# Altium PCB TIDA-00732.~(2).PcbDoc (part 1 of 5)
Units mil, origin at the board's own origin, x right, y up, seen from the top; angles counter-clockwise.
Board outline 8994.78 x 4186 mil, 6 copper layers (Top Layer, GND1, PWR1, PWR2, GND2, Bottom Layer), stack 97.668 mil thick; 693 components, 463 nets, 2087 pads, 616 vias.
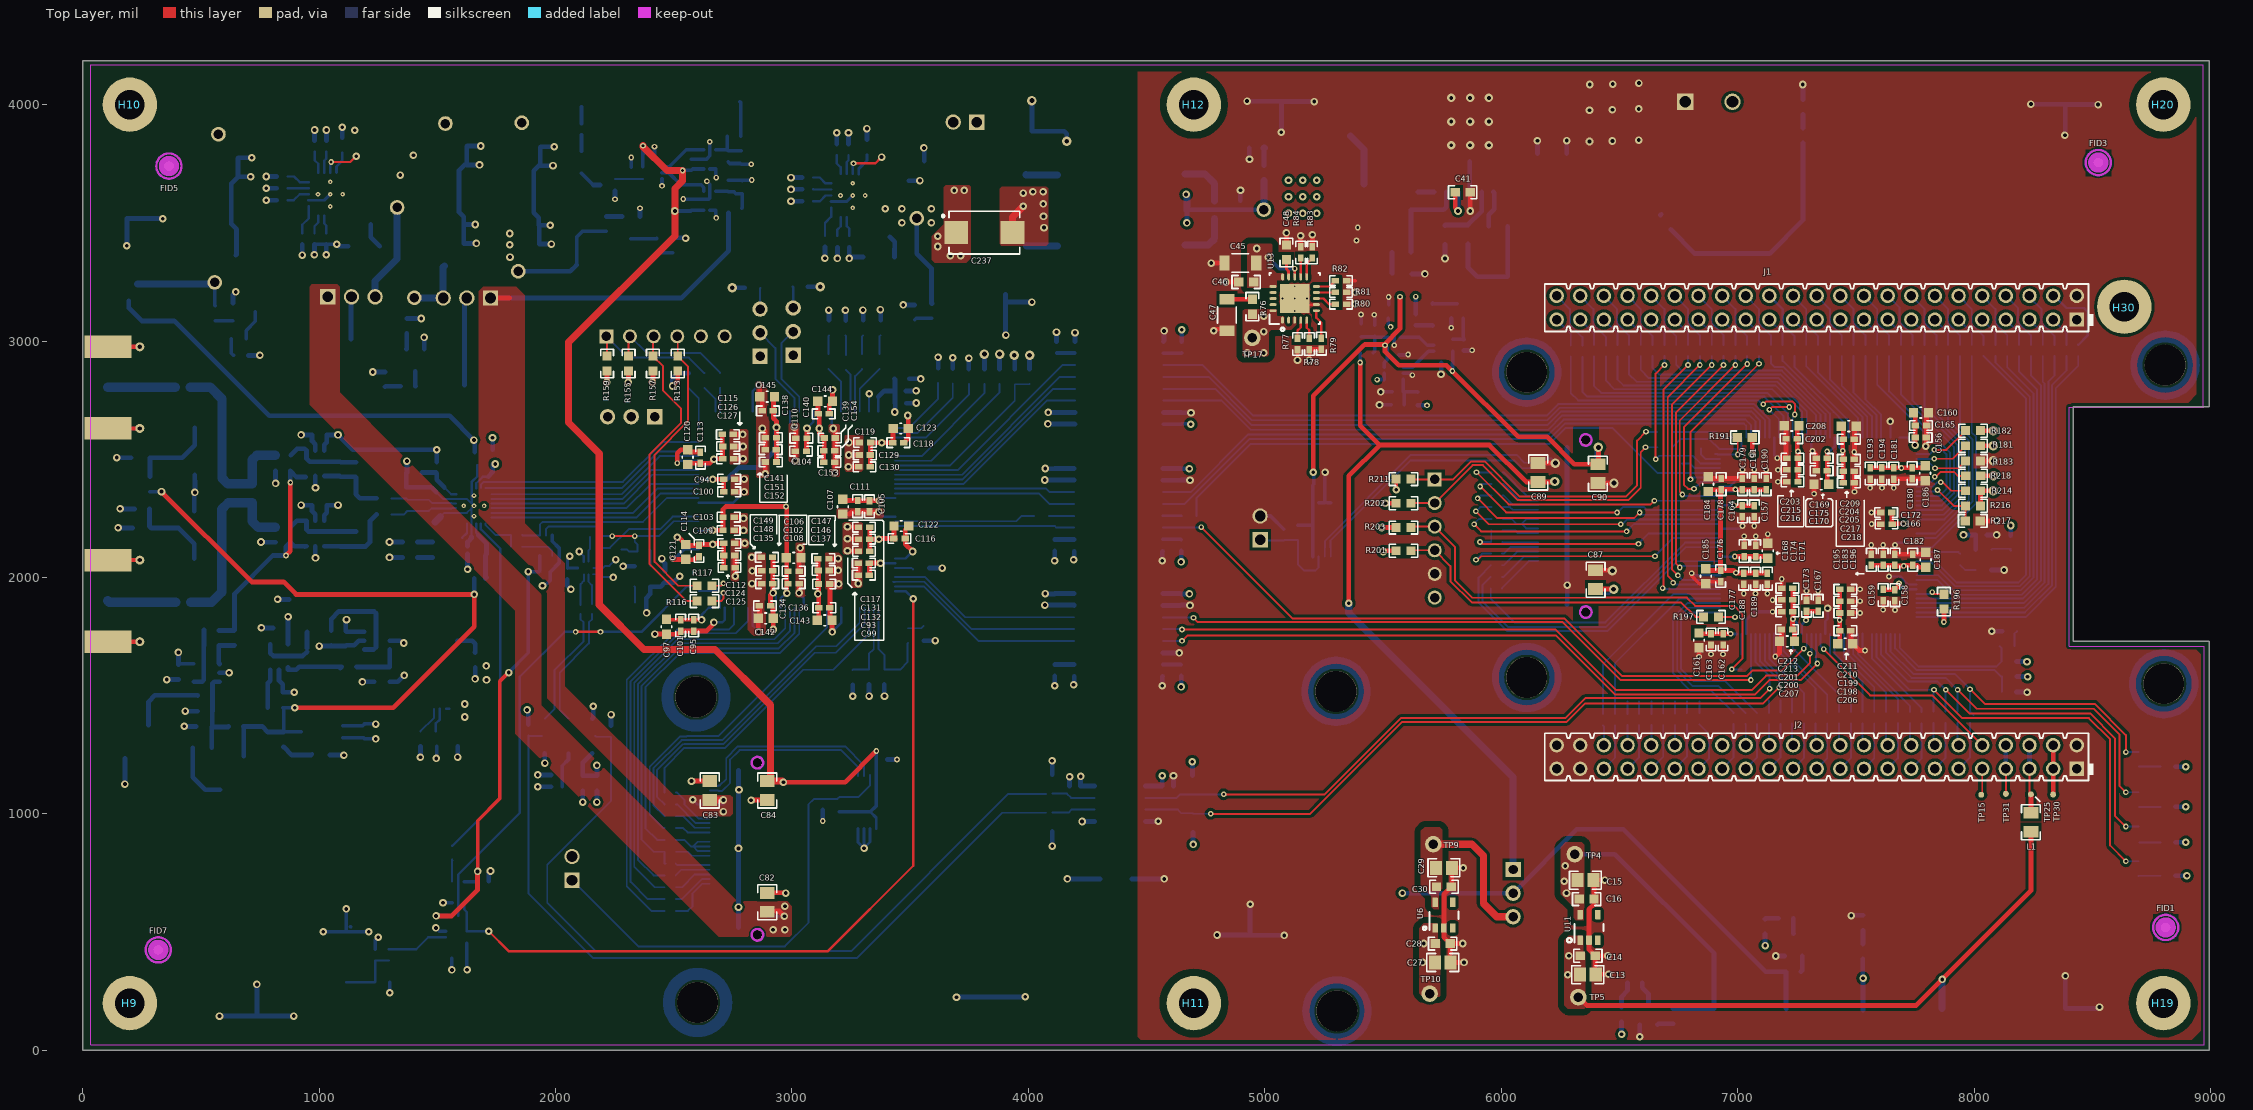
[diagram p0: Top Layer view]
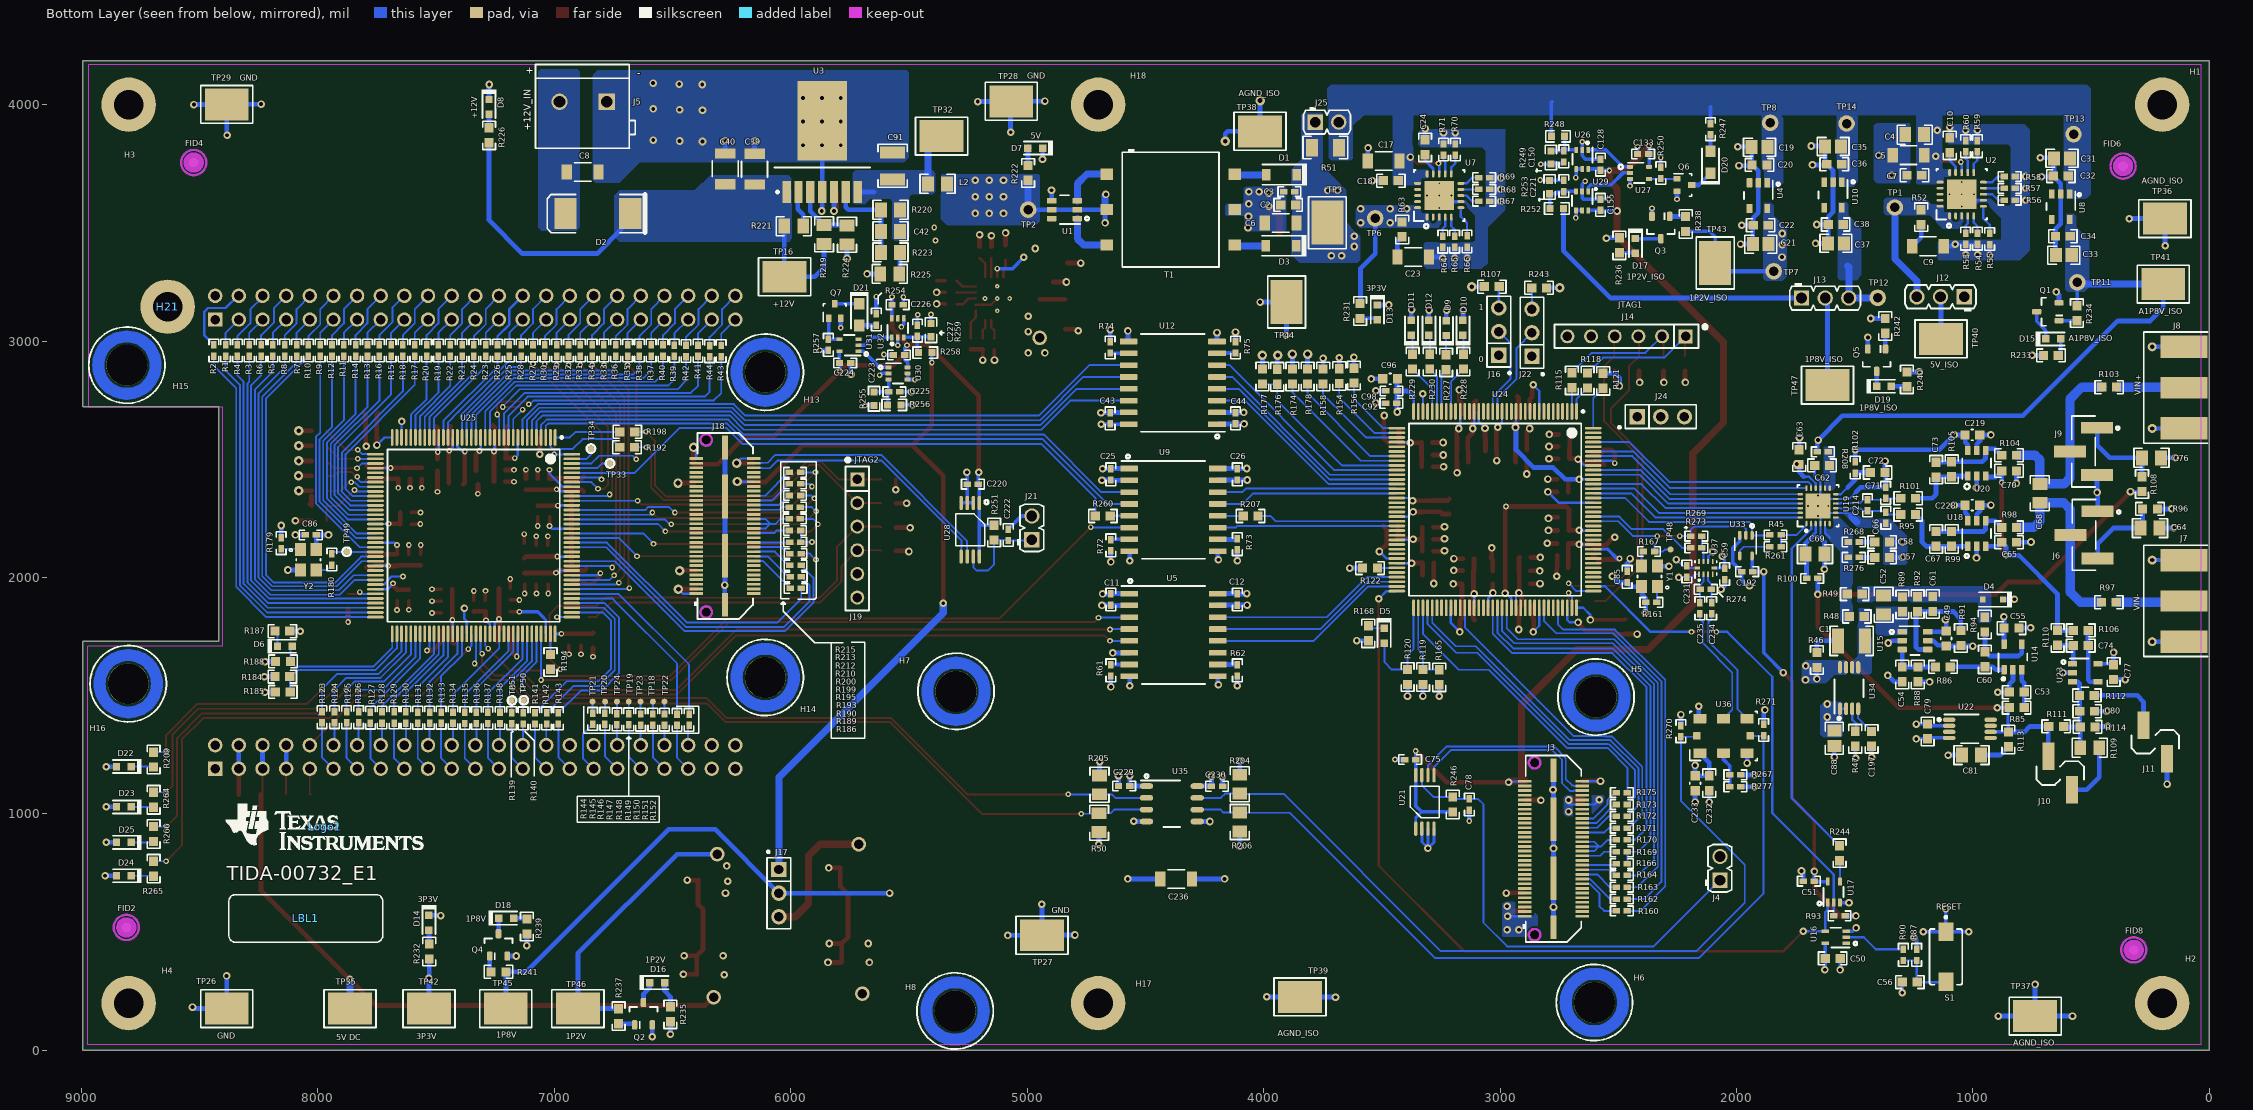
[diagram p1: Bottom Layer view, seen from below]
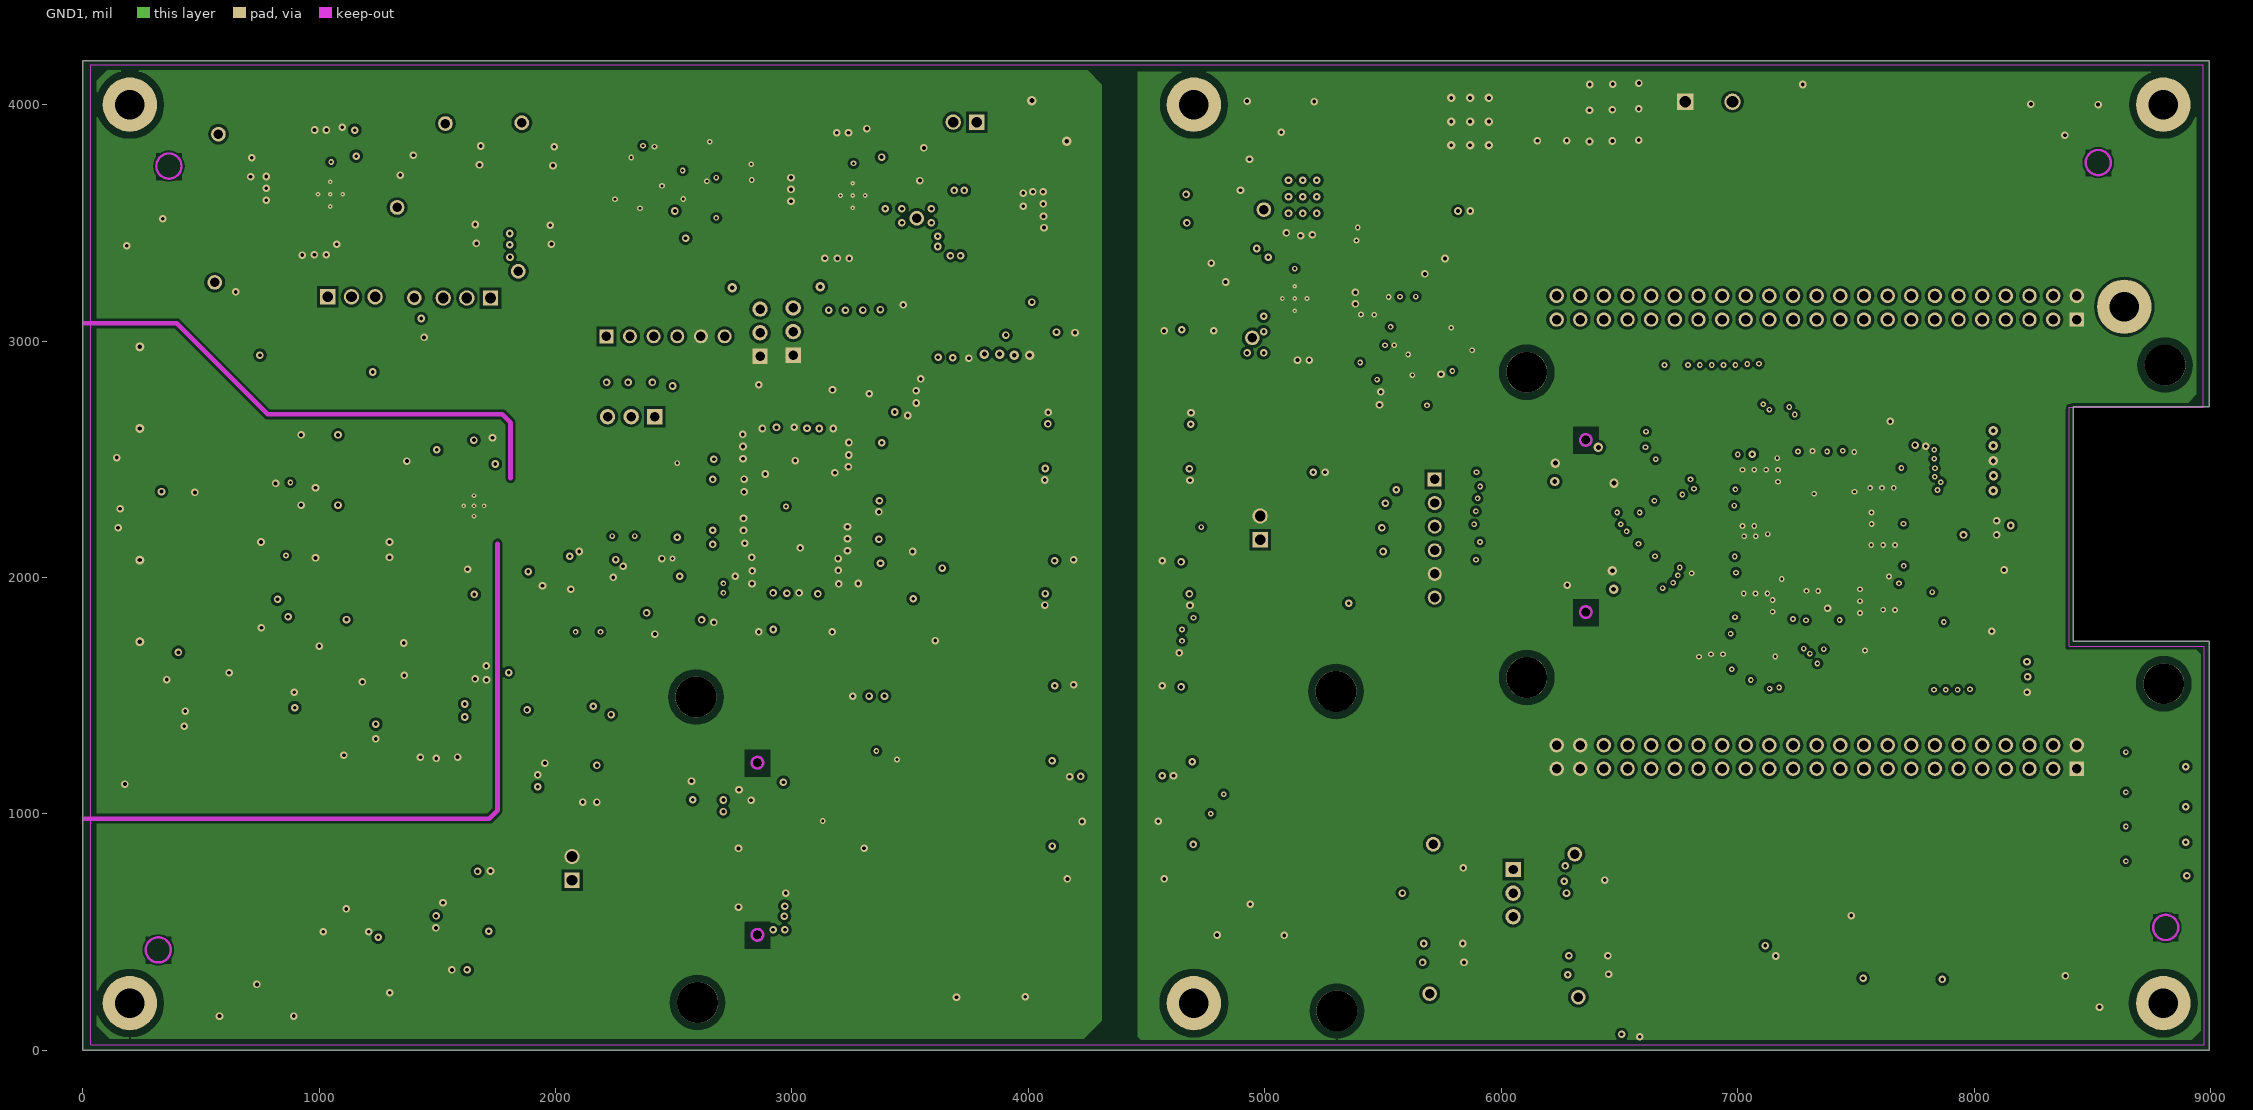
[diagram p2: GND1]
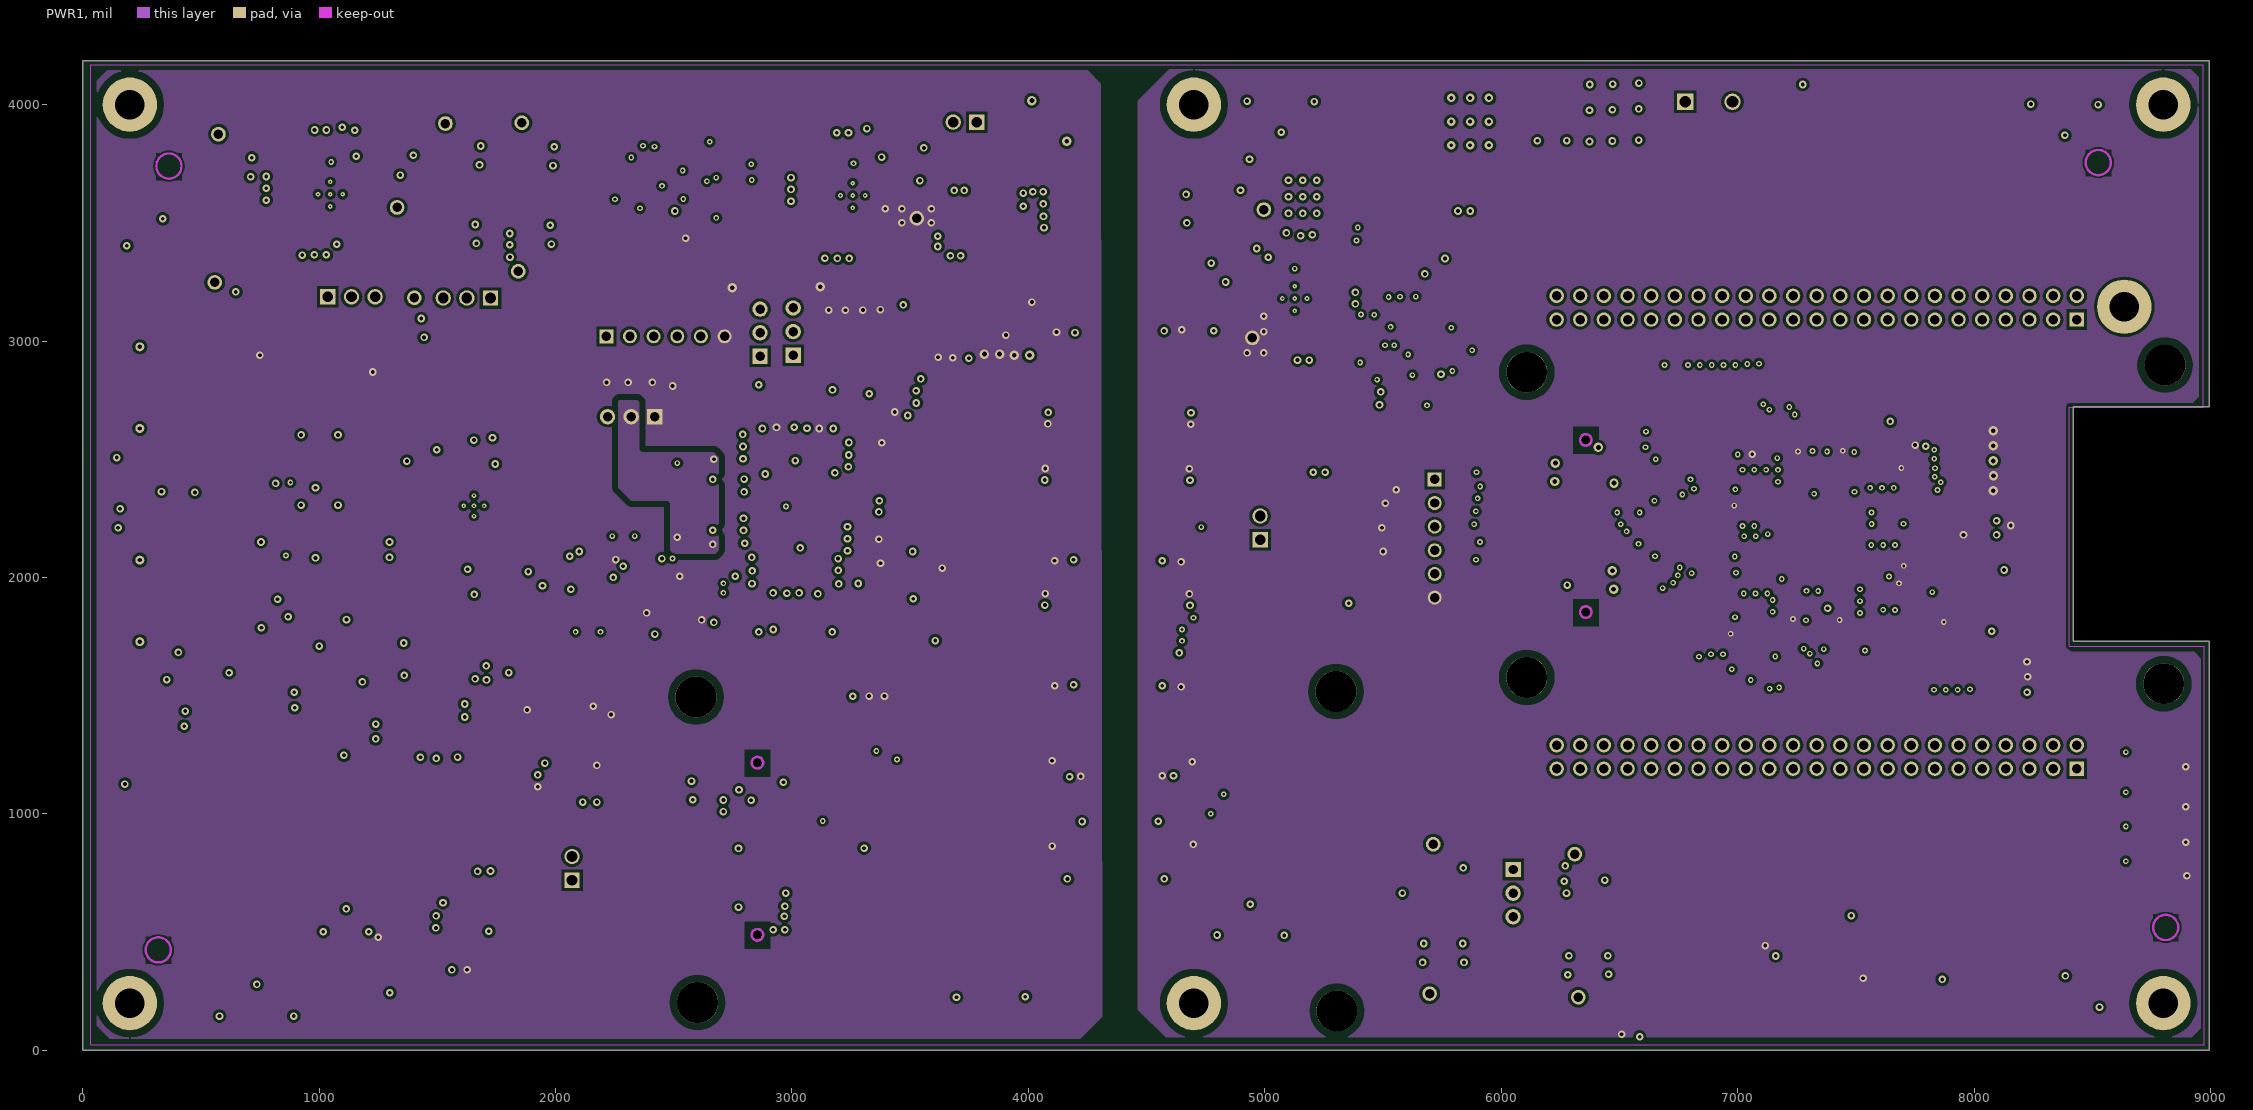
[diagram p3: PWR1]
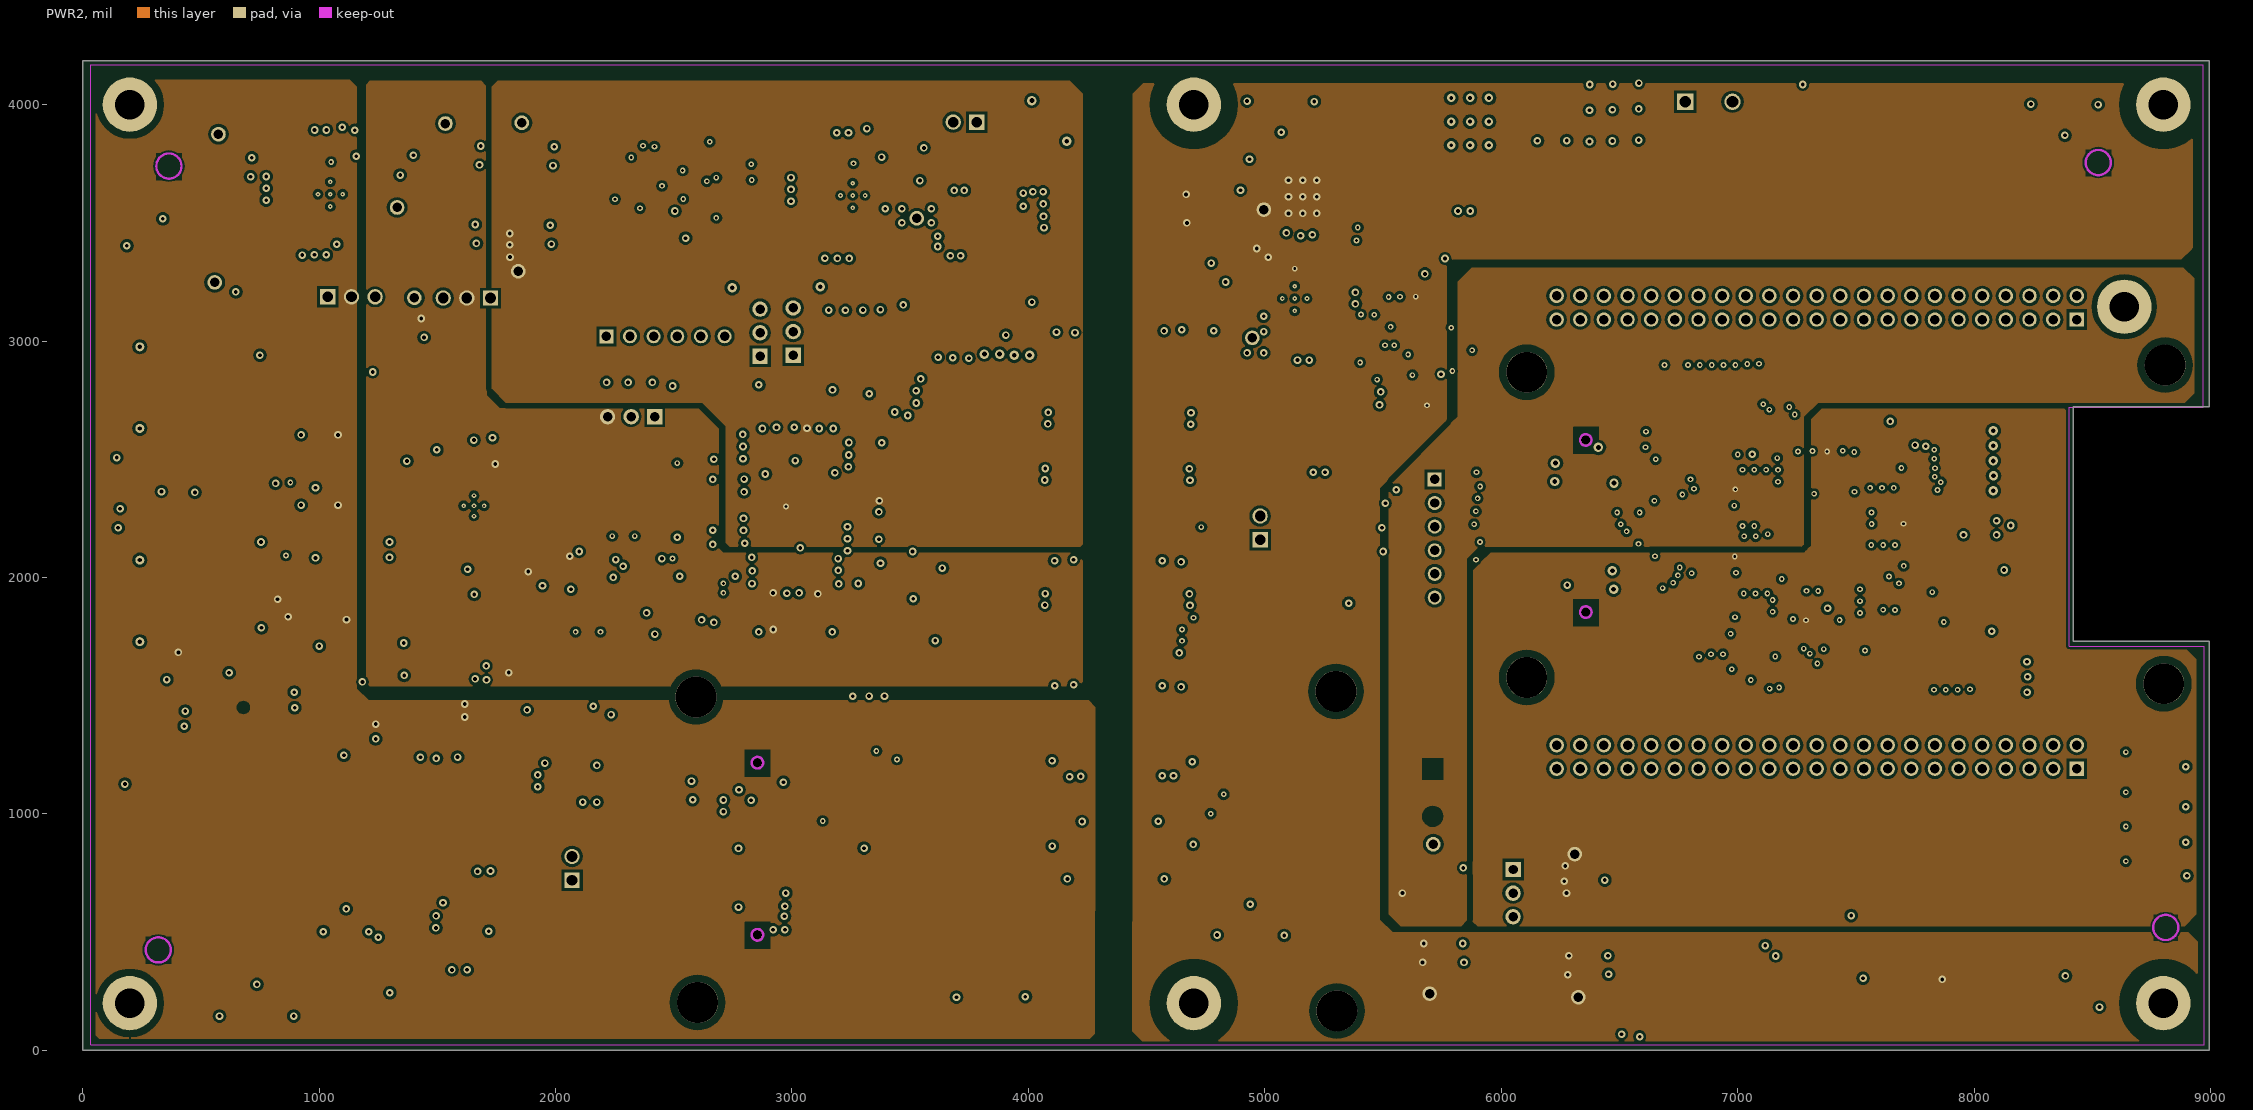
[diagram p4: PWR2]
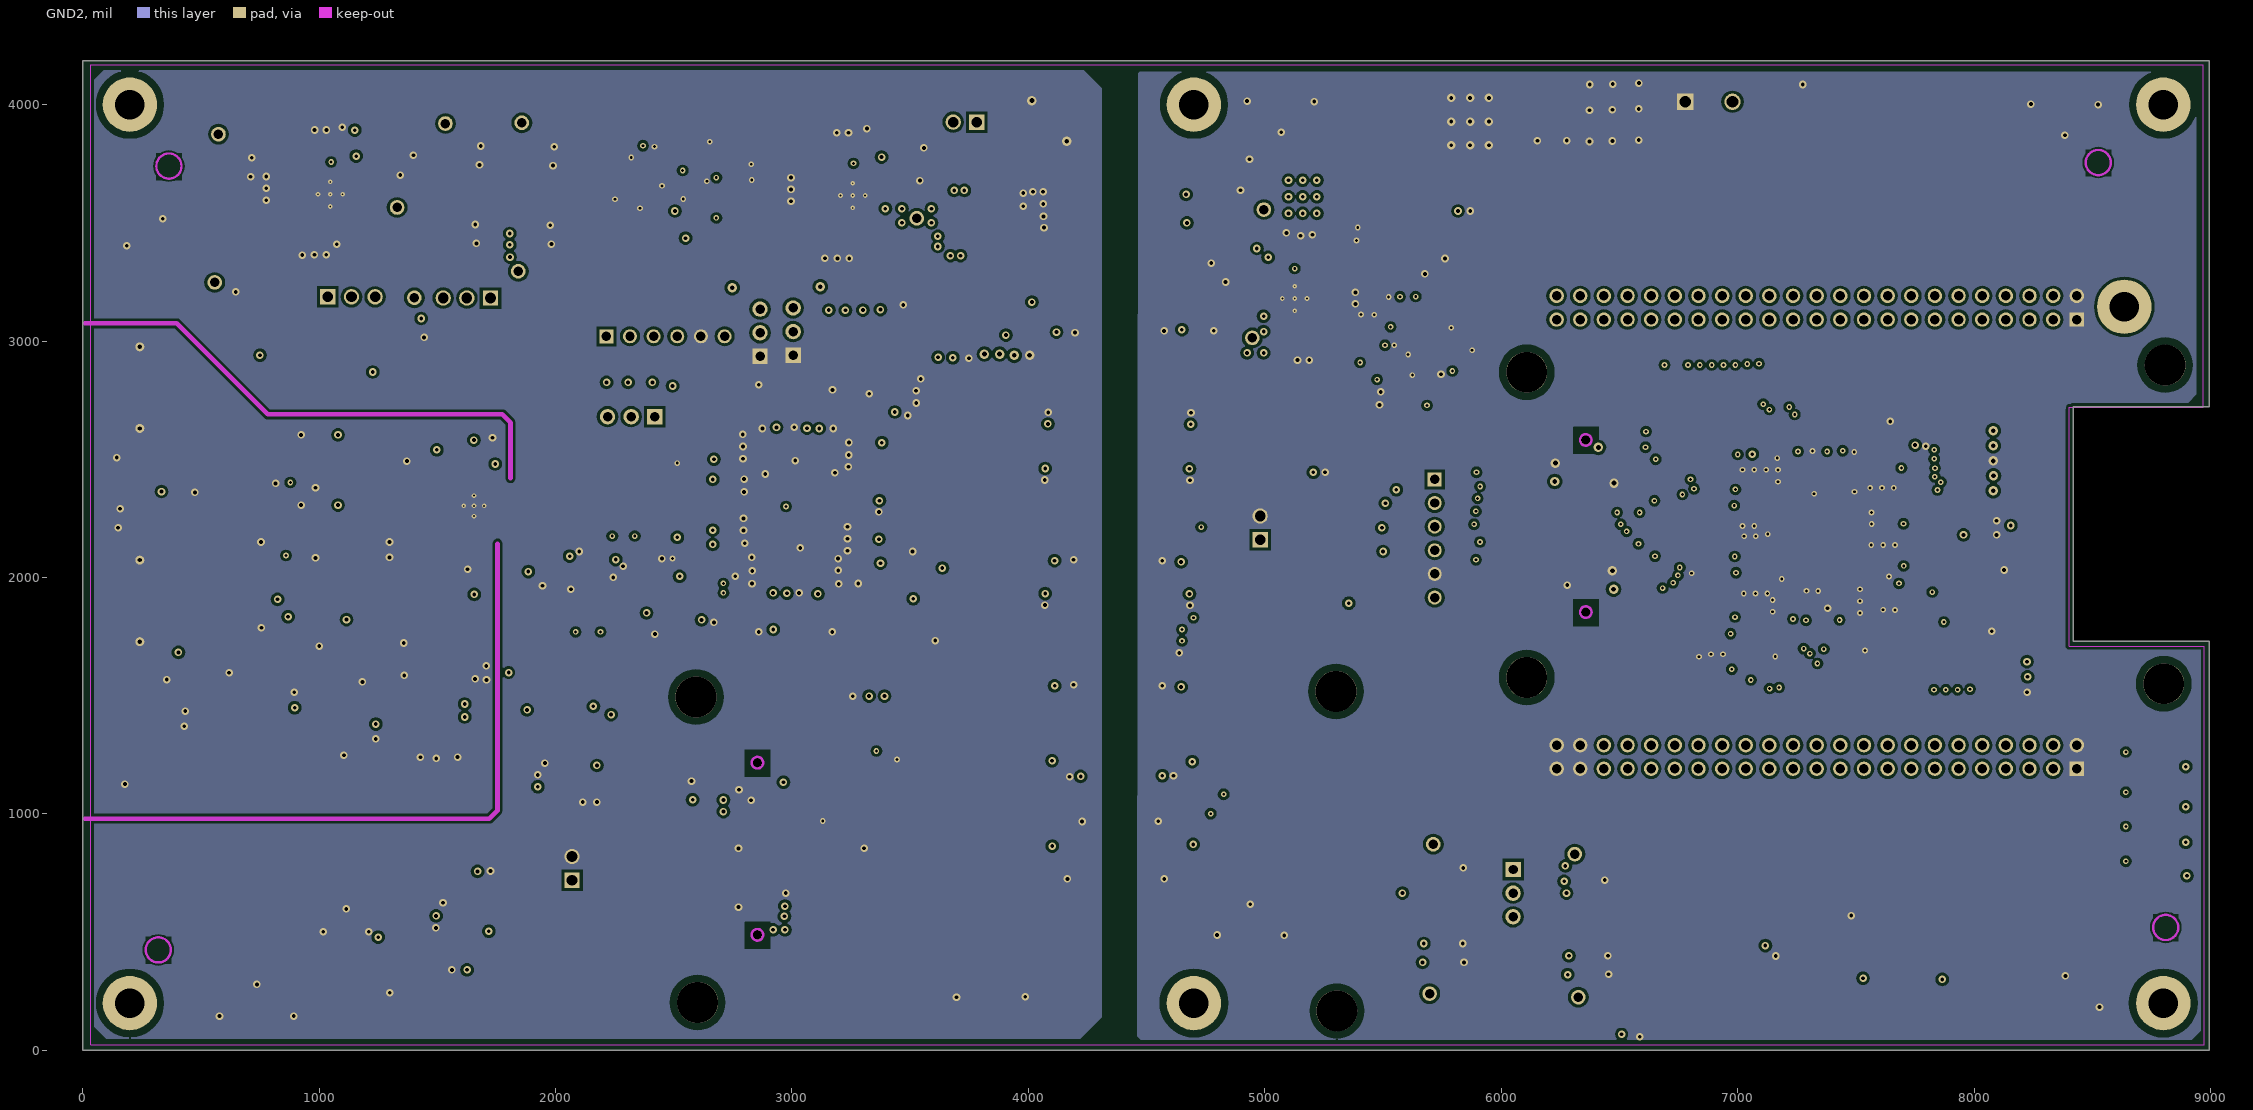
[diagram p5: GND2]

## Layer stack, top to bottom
Top Solder: solder mask 0.4, Solder Resist, Dk 3.5
Top Layer: signal copper 1.4
Dielectric1: core 59.2, FR-4, Dk 4.8
GND1: signal copper 1.417
Dielectric 2: core 10, Dk 4.2
PWR1: signal copper 1.417
Dielectric 3: prepreg 5, Dk 4.2
PWR2: signal copper 1.417
Dielectric 5: prepreg 5, Dk 4.2
GND2: signal copper 1.417
Dielectric 4: core 10, Dk 4.2
Bottom Layer: signal copper 1.4
Bottom Solder: solder mask 0.4, Solder Resist, Dk 3.5

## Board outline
0,0 0,4186 8994.78,4186 8994.78,2722 8419.78,2722 8419.78,1730 8994.78,1730 8994.78,0

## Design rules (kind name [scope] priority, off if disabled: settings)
AcuteAngle [All] p1: minimum=4.50000000000000E+0001 checktracksonly=FALSE
AssemblyTestPointUsage [All] p1: valid=2
Clearance "Clearance_MH to Copper" [InPadClass('MH') vs InPolygon] p1: gap=30
Clearance Clearance_Poly [InPolygon vs InPolygon] p2: gap=25
Clearance "Clearance_Poly to All" [IsVia or IsTrack or IsSMTPin or IsThruPin vs InPolygon] p3: gap=12
Clearance "Via to Via" [IsVia vs IsVia] p4: gap=8
Clearance "Via 2 SMD PAD" [IsVia vs IsSMTPin] p5: gap=8
Clearance Clearance_PadClass [InPadClass('U1') vs InPadClass('U1')] p6: gap=7.8
Clearance [All] p7: gap=7.7
ComponentClearance ComponentClearance_Shunt [InComponentClass('Header') vs InComponentClass('Shunt')] p1: gap=0 collisioncheckmode=3 verticalgap=0 showdistances=FALSE
ComponentClearance ComponentClearance_Logo [InComponentClass('Logo')] p2: gap=50 collisioncheckmode=3 verticalgap=10 showdistances=FALSE
ComponentClearance ComponentClearance_ScrewToNut [(HasFootprint('NY PMS 440 0025 PH')) vs (HasFootprint('Keystone_1902C'))] p3: gap=5 collisioncheckmode=3 verticalgap=10 showdistances=FALSE
ComponentClearance ComponentClearance_MountingHoles [InComponentClass('Mounting Holes')] p4: gap=250 collisioncheckmode=3 verticalgap=100000 showdistances=FALSE
ComponentClearance ComponentClearance_SmallPassives [HasFootprint('0201*') or HasFootprint('0402*') or HasFootprint('0508') or HasFootprint('0603*') or HasFootprint('0612') or HasFootprint('0805*') or HasFootprint('0815*') or HasFootprint('0830*') or HasFootprint('1206*') or HasFootprint('1210*') or HasFootprint('1808*') or HasFootprint('1812*') or HasFootprint('1825*') or HasFootprint('2010*') or HasFootprint('2220*') or HasFootprint('2225*') or HasFootprint('2512*') or HasFootprint('2728*') or HasFootprint('3518*') vs HasFootprint('0201*') or HasFootprint('0402*') or HasFootprint('0508') or HasFootprint('0603*') or HasFootprint('0612') or HasFootprint('0805*') or HasFootprint('0815*') or HasFootprint('0830*') or HasFootprint('1206*') or HasFootprint('1210*') or HasFootprint('1808*') or HasFootprint('1812*') or HasFootprint('1825*') or HasFootprint('2010*') or HasFootprint('2220*') or HasFootprint('2225*') or HasFootprint('2512*') or HasFootprint('2728*') or HasFootprint('3518*')] p5: gap=20 collisioncheckmode=3 verticalgap=10 showdistances=FALSE
ComponentClearance ComponentClearance_THtoSMT [IsThruComponent vs IsSMTComponent] p6: gap=100 collisioncheckmode=3 verticalgap=30 showdistances=FALSE
ComponentClearance ComponentClearance_THtoTH [IsThruComponent vs IsThruComponent] p7: gap=118.11 collisioncheckmode=3 verticalgap=30 showdistances=FALSE
ComponentClearance [All] p8: gap=40 collisioncheckmode=3 verticalgap=10 showdistances=FALSE
DiffPairsRouting DiffPair_DiffPairsRouting [InDifferentialPair ('BCLK')] p1: maxlimit=15 minlimit=15 mostfreqgap=15 toplayer_minwidth=8 toplayer_maxwidth=8 toplayer_prefwidth=8 midlayer1_minwidth=8 midlayer1_maxwidth=8 midlayer1_prefwidth=8 midlayer2_minwidth=8 midlayer2_maxwidth=8 midlayer2_prefwidth=8 midlayer3_minwidth=8 midlayer3_maxwidth=8 midlayer3_prefwidth=8 midlayer4_minwidth=8 midlayer4_maxwidth=8 midlayer4_prefwidth=8 bottomlayer_minwidth=8 bottomlayer_maxwidth=8 bottomlayer_prefwidth=8 maxuncoupledlength=500
DiffPairsRouting DiffPair_DiffPairsRouting_1 [InDifferentialPair ('NewDifferentialPair1')] p2: maxlimit=15 minlimit=15 mostfreqgap=15 toplayer_minwidth=8 toplayer_maxwidth=8 toplayer_prefwidth=8 midlayer1_minwidth=8 midlayer1_maxwidth=8 midlayer1_prefwidth=8 midlayer2_minwidth=8 midlayer2_maxwidth=8 midlayer2_prefwidth=8 midlayer3_minwidth=8 midlayer3_maxwidth=8 midlayer3_prefwidth=8 midlayer4_minwidth=8 midlayer4_maxwidth=8 midlayer4_prefwidth=8 bottomlayer_minwidth=8 bottomlayer_maxwidth=8 bottomlayer_prefwidth=8 maxuncoupledlength=500
DiffPairsRouting DiffPair_DiffPairsRouting_1_1 [InDifferentialPair ('NewDifferentialPair1')] p3: maxlimit=15 minlimit=15 mostfreqgap=15 toplayer_minwidth=8 toplayer_maxwidth=8 toplayer_prefwidth=8 midlayer1_minwidth=8 midlayer1_maxwidth=8 midlayer1_prefwidth=8 midlayer2_minwidth=8 midlayer2_maxwidth=8 midlayer2_prefwidth=8 midlayer3_minwidth=8 midlayer3_maxwidth=8 midlayer3_prefwidth=8 midlayer4_minwidth=8 midlayer4_maxwidth=8 midlayer4_prefwidth=8 bottomlayer_minwidth=8 bottomlayer_maxwidth=8 bottomlayer_prefwidth=8 maxuncoupledlength=500
DiffPairsRouting DiffPair_DiffPairsRouting_2 [InDifferentialPair ('NewDifferentialPair1')] p4: maxlimit=15 minlimit=15 mostfreqgap=15 toplayer_minwidth=8 toplayer_maxwidth=8 toplayer_prefwidth=8 midlayer1_minwidth=8 midlayer1_maxwidth=8 midlayer1_prefwidth=8 midlayer2_minwidth=8 midlayer2_maxwidth=8 midlayer2_prefwidth=8 midlayer3_minwidth=8 midlayer3_maxwidth=8 midlayer3_prefwidth=8 midlayer4_minwidth=8 midlayer4_maxwidth=8 midlayer4_prefwidth=8 bottomlayer_minwidth=8 bottomlayer_maxwidth=8 bottomlayer_prefwidth=8 maxuncoupledlength=500
DiffPairsRouting DiffPair_DiffPairsRouting_1_1_1 [InDifferentialPair ('AIN')] p5: maxlimit=15 minlimit=15 mostfreqgap=15 toplayer_minwidth=8 toplayer_maxwidth=18 toplayer_prefwidth=8 midlayer1_minwidth=8 midlayer1_maxwidth=18 midlayer1_prefwidth=8 midlayer2_minwidth=8 midlayer2_maxwidth=18 midlayer2_prefwidth=8 midlayer3_minwidth=8 midlayer3_maxwidth=18 midlayer3_prefwidth=8 midlayer4_minwidth=8 midlayer4_maxwidth=18 midlayer4_prefwidth=8 bottomlayer_minwidth=8 bottomlayer_maxwidth=18 bottomlayer_prefwidth=8 maxuncoupledlength=500
FabricationTestPointUsage TestPointUsage [All] p1: valid=2 allowmultiple=FALSE
FabricationTestpoint Testpoint [All] p1: side=3 testpointundercomponent=TRUE minsize=40 maxsize=100 preferedsize=60 minholesize=0 maxholesize=40 preferedholesize=32 testpointgrid=1 allowsidetop=TRUE allowsidebottom=TRUE usegrid=TRUE gridtolerance=0.01
FanoutControl Fanout_LCC [IsLCC] p1: bgadir=Out bgaviamode=Centered fanoutstyle=Auto fanoutdirection=Alternating viagrid=1 // Fanout_LCC (Default Rule)
FanoutControl Fanout_BGA [IsBGA] p2: bgadir=Out bgaviamode=Centered fanoutstyle=Auto fanoutdirection=Alternating viagrid=1 // Fanout_BGA (Default Rule)
FanoutControl Fanout_Default [All] p4: bgadir=Out bgaviamode=Centered fanoutstyle=Auto fanoutdirection=Alternating viagrid=1 // Fanout_Default (Default Rule)
FanoutControl Fanout_Small [(CompPinCount < 5)] p5: bgadir=Out bgaviamode=Centered fanoutstyle=Auto fanoutdirection=OutThenIn viagrid=1 // Fanout_Small (Default Rule)
HoleSize [All] p1: absolutevalues=TRUE maxlimit=251 minlimit=7.87 maxpercent=80.000 minpercent=20.000
MatchedLengths DiffPair_MatchedLengths [InDifferentialPair ('BCLK')] p1: tolerance=1000 checknetsindiffpair=TRUE checkdiffpairvsdiffpair=TRUE checkothers=TRUE
MatchedLengths DiffPair_MatchedLengths_1 [InDifferentialPair ('NewDifferentialPair1')] p2: tolerance=1000 checknetsindiffpair=TRUE checkdiffpairvsdiffpair=TRUE checkothers=TRUE
MatchedLengths DiffPair_MatchedLengths_1_1 [InDifferentialPair ('NewDifferentialPair1')] p3: tolerance=1000 checknetsindiffpair=TRUE checkdiffpairvsdiffpair=TRUE checkothers=TRUE
MatchedLengths DiffPair_MatchedLengths_2 [InDifferentialPair ('NewDifferentialPair1')] p4: tolerance=1000 checknetsindiffpair=TRUE checkdiffpairvsdiffpair=TRUE checkothers=TRUE
MatchedLengths DiffPair_MatchedLengths_1_2 [InDifferentialPair ('AIN')] p5: tolerance=1000 checknetsindiffpair=TRUE checkdiffpairvsdiffpair=TRUE checkothers=TRUE
MatchedLengths DiffPair_MatchedLengths_1_1_1 [InDifferentialPair ('AIN')] p6: tolerance=1000 checknetsindiffpair=TRUE checkdiffpairvsdiffpair=TRUE checkothers=TRUE
MinimumAnnularRing MinimumAnnularRing_ThermalPadVias [IsVia and InAnyComponent] p1: minimumring=5.91
MinimumAnnularRing [All] p2: minimumring=5
MinimumSolderMaskSliver MinimumSolderMaskSliver_Logo [InComponentClass('Logo') vs InComponentClass('Logo')] p1: minsoldermaskwidth=0.7
MinimumSolderMaskSliver [All] p2: minsoldermaskwidth=3.94
PlaneConnect [All] p1: planeconnectstyle=Relief reliefexpansion=10 reliefentries=4 reliefconductorwidth=10 reliefairgap=10
PolygonConnect [All] p1: connectstyle=Direct reliefconductorwidth=20 reliefentries=4 polygonreliefangle="90 Angle" airgapwidth=15
RoutingVias ThermalPadVias [IsVia and InAnyComponent] p1: holewidth=7.87 width=19.68 viastyle="Through Hole" minholewidth=7.87 minwidth=19.68 maxholewidth=12.99 maxwidth=23.62
RoutingVias [All] p2: holewidth=16 width=32 viastyle="Through Hole" minholewidth=12 minwidth=24 maxholewidth=20 maxwidth=40
SMDToCorner [All] p1: distance=30000
SilkToSilkClearance [All] p1: silktosilkclearance=5
SilkToSolderMaskClearance SilkscreenOverComponentPads [IsPad] p1: minsilkscreentomaskgap=5 clearancetoexposedcopper=TRUE
SolderMaskExpansion [All] p1: expansion=2.5
UnpouredPolygon [All] p1: allowunpoured=FALSE
Width [All] p1: maxlimit=100 minlimit=6 preferedwidth=8 checkconnectedcopper=TRUE
15 further rules are at their usual default settings.

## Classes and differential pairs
component class TIDA-00732_Isolator: C2 C3 C4 C5 C6 C7 C8 C9 C10 C11 C12 C25 C26 C39 C40 C41 C42 C43 C44 C91 C229 C230 C236 C237 D1 D2 D3 D7 D8 J5 J25 L2 R50 R51 R52 R53 R54 R55 R56 R57 R58 R59 R60 R61 R62 R72 R73 R74 R75 R204 R205 R206 R207 R219 R220 R221 R222 R223 R224 R225 R226 R260 T1 TP1 TP2 TP3 TP16 TP26 TP27 TP28 TP29 TP32 TP35 TP36 TP37 TP38 TP39 TP40 TP41 TP42 TP43 TP44 TP45 TP46 TP47 U1 U2 U3 U5 U9 U12 U35
component class TIDA-00732_FPGA_2: C86 C156 C157 C158 C159 C160 C161 C162 C163 C164 C165 C166 C167 C168 C169 C170 C171 C172 C173 C174 C175 C176 C177 C178 C179 C180 C181 C182 C183 C184 C185 C186 C187 C188 C189 C190 C191 C193 C194 C195 C196 C198 C199 C200 C201 C202 C203 C204 C205 C206 C207 C208 C209 C210 C211 C212 C213 C215 C216 C217 C218 D6 D22 D23 D24 D25 J19 R179 R180 R181 R182 R183 R184 R185 R187 R188 R191 R192 R194 R196 R197 R198 R201 R202 R203 R209 R211 R214 R216 R217 R218 R264 R265 R266 TP33 TP34 TP49 U25 Y2
component class Header: J1 J2 J4 J6 J9 J10 J11 J12 J13 J14 J16 J17 J19 J21 J22 J24 J25
component class TIDA-00732_Connector: C75 C78 C82 C83 C84 C87 C89 C90 C220 C222 J1 J2 J3 J4 J18 J21 L1 R1 R2 R3 R4 R5 R6 R7 R8 R9 R10 R11 R12 R13 R14 R15 R16 R17 R18 R19 R20 R21 R22 R23 R24 R25 R26 R27 R28 R29 R30 R31 R32 R33 R34 R35 R36 R37 R38 R39 R40 R41 R42 R43 R44 R123 R124 R125 R126 R127 R128 R129 R130 R131 R132 R133 R134 R135 R136 R137 R138 R139 R140 R141 R142 R143 R144 R145 R146 R147 R148 R149 R150 R151 R152 R160 R162 R163 R164 R166 R169 R170 R171 R172 R173 R175 R186 R189 R190 R193 R195 R199 R200 R210 R212 R213 R215 R246 R251 TP15 TP18 TP19 TP20 TP21 TP22 TP23 TP24 TP25 TP30 TP31 TP50 TP51 U21 U28
component class Label: LBL1
component class AssemblyNote: ZZ1 ZZ2 ZZ3 ZZ4
component class FiducialMark: FID1 FID2 FID3 FID4 FID5 FID6 FID7 FID8
component class TIDA-00732_TID_Hardware: FID1 FID2 FID3 FID4 FID5 FID6 FID7 FID8 H1 H2 H3 H4 H5 H6 H7 H8 H9 H10 H11 H12 H13 H14 H15 H16 H17 H18 H19 H20 H21 H30 LBL1 Logo1 ZZ1 ZZ2 ZZ3 ZZ4
component class Logo: Logo1
pad class MH: H1-1 H2-1 H3-1 H4-1 H5- H6- H7- H8- H9-0 H10-0 H11-0 H12-0 H13- H14- H15- H16- H17-1 H18-1 H19-0 H120-0
component class TIDA-00732_Pwr: C13 C14 C15 C16 C17 C18 C19 C20 C21 C22 C23 C24 C27 C28 C29 C30 C31 C32 C33 C34 C35 C36 C37 C38 C45 C46 C47 C48 D13 D14 D15 D16 D17 D18 D19 J12 J13 J17 Q1 Q2 Q3 Q4 Q5 R63 R64 R65 R66 R67 R68 R69 R70 R71 R76 R77 R78 R79 R80 R81 R82 R83 R84 R231 R232 R233 R234 R235 R236 R237 R238 R239 R240 R241 R242 TP4 TP5 TP6 TP7 TP8 TP9 TP10 TP11 TP12 TP13 TP14 TP17 U4 U6 U7 U8 U10 U11 U13
component class TIDA-00732_ADC: C50 C51 C56 C62 C63 C64 C65 C66 C67 C68 C69 C70 C71 C72 C73 C76 C192 C214 C219 C228 J6 J7 J8 J9 R45 R87 R90 R93 R95 R96 R97 R98 R99 R100 R101 R102 R103 R104 R105 R108 R208 R244 R261 S1 U16 U17 U18 U19 U20 U33
component class TIDA-00732_FPGA_1: C85 C92 C93 C94 C95 C96 C97 C98 C99 C100 C101 C102 C103 C104 C105 C106 C107 C108 C109 C110 C111 C112 C113 C114 C115 C116 C117 C118 C119 C120 C121 C122 C123 C124 C125 C126 C127 C129 C130 C131 C132 C134 C135 C136 C137 C138 C139 C140 C141 C142 C143 C144 C145 C146 C147 C148 C149 C151 C152 C153 C154 D5 D9 D10 D11 D12 J14 J16 J22 J24 R107 R115 R116 R117 R118 R119 R120 R121 R122 R153 R154 R155 R156 R157 R158 R159 R161 R165 R167 R168 R174 R176 R177 R178 R227 R228 R229 R230 R243 TP48 U24 Y1
component class TIDA-00732_Pwr_Sense: C128 C133 C150 C155 C221 C223 C224 C225 C226 C227 D20 D21 Q6 Q7 R247 R248 R249 R250 R252 R253 R254 R255 R256 R257 R258 R259 U26 U27 U29 U30 U31 U32
component class TIDA-00732_ADC_Ref_Select: C1 C49 C52 C53 C54 C55 C57 C58 C59 C60 C61 C74 C77 C79 C80 C81 C88 C197 C231 C232 C233 C234 C235 D4 J10 J11 R46 R47 R48 R49 R85 R86 R88 R89 R91 R92 R94 R106 R109 R110 R111 R112 R113 R114 R267 R268 R269 R270 R271 R273 R274 R276 R277 U14 U15 U22 U23 U34 U36 U37
differential pair BCLK: +BCLK_P -BCLK_N

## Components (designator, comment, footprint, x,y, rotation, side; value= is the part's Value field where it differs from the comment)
C1 "GRM32ER71A476KE15L" 1210 1513,1732 r180 bottom
C2 "GRM188R71E105KA12D" 0603#1 3896,3576 r0 bottom
C3 "GRM155R71C104KA88D" 0402 3891,3632 r180 bottom
C4 "GRM21BR71A106KE51L" 0805_HV 1246.35,3872.99 r0 bottom
C5 "C3216X5R1E476M160AC" 1206_190 1272.52,3785.92 r0 bottom
C6 "C3216X7R1E106M160AE" 1206_190 3928,3499 r0 bottom
C7 "GRM1885C1H102FA01J" 0603#1 1247.52,3700.92 r0 bottom
C8 "C3216X7R1E106M160AE" 1206_190 6880,3715 r180 bottom
C9 "C3216X5R1E476M160AC" 1206_190 1190,3401 r180 bottom
C10 "GRM188R71E105KA12D" 0603#1 1098,3828 r270 bottom
C11 "GRM155R71C104KA88D" 0402 4646.01,1906.99 r90 bottom
C12 "GRM155R71C104KA88D" 0402 4111.01,1906.99 r270 bottom
C13 "08055C105KAT2A" 0805 6365.93,320.04 r0 top
C14 "C0603C104K5RACTU" 0603#1 6365.93,400.04 r0 top
C15 "0805YD106MAT2A" 0805 6355.93,720.04 r0 top
C16 "C0603C104K5RACTU" 0603#1 6360.93,640.04 r0 top
C17 "C3216X5R1E476M160AC" 1206_190 3492.18,3761.46 r0 bottom
C18 "GRM1885C1H102FA01J" 0603#1 3462.18,3678.46 r0 bottom
C19 "08055C105KAT2A" 0805 1902.5,3820 r0 bottom
C20 "C0603C104K5RACTU" 0603#1 1902.5,3745 r0 bottom
C21 "0805YD106MAT2A" 0805 1897.5,3410 r0 bottom
C22 "C0603C104K5RACTU" 0603#1 1897.5,3490 r0 bottom
C23 "C3216X5R1E476M160AC" 1206_190 3367,3355 r180 bottom
C24 "GRM188R71E105KA12D" 0603#1 3317.18,3819.46 r270 bottom
C25 "GRM155R71C104KA88D" 0402 4646,2435.98 r90 bottom
C26 "GRM155R71C104KA88D" 0402 4111,2435.98 r270 bottom
C27 "08055C105KAT2A" 0805 5752.35,371.88 r0 top
C28 "C0603C104K5RACTU" 0603#1 5752.35,451.88 r0 top
C29 "0805YD106MAT2A" 0805 5757.35,771.88 r0 top
C30 "C0603C104K5RACTU" 0603#1 5757.35,691.88 r0 top
C31 "08055C105KAT2A" 0805 623.5,3773 r0 bottom
C32 "C0603C104K5RACTU" 0603#1 628.5,3698 r0 bottom
C33 "0805YD106MAT2A" 0805 615.5,3363 r0 bottom
C34 "C0603C104K5RACTU" 0603#1 619.5,3443 r0 bottom
C35 "08055C105KAT2A" 0805 1591.5,3823 r0 bottom
C36 "C0603C104K5RACTU" 0603#1 1586.5,3748 r0 bottom
C37 "0805YD106MAT2A" 0805 1579.5,3413 r0 bottom
C38 "C0603C104K5RACTU" 0603#1 1580.5,3493 r0 bottom
C39 "UMK325AB7106KM-T" 1210_280 6153,3727 r90 bottom
C40 "UMK325AB7106KM-T" 1210_280 6277,3728 r90 bottom
C41 "C0603C103J5RACTU" 0603#1 5837,3629 r0 top
C42 "08055C223KAT2A" 0805_HV 5578,3464 r0 bottom
C43 "GRM155R71C104KA88D" 0402 4649,2673 r90 bottom
C44 "GRM155R71C104KA88D" 0402 4119,2673 r270 bottom
C45 "C3216X5R1E476M160AC" 1206_190 4896.25,3329.76 r180 top
C46 "GRM1885C1H102FA01J" 0603#1 4921.25,3249.76 r180 top
C47 "C3216X5R1E476M160AC" 1206_190 4839.25,3110.3 r270 top
C48 "GRM188R71E105KA12D" 0603#1 5091.25,3374.76 r270 top
C49 "ZRB18AD71A106KE01L" 0603_120 1113,1742 r90 bottom
C50 "0603YC104JAT2A" 0603#1 1593.13,388.73 r0 bottom
C51 "GRM155R71C104KA88D" 0402 1694.13,715.73 r180 bottom
C52 "0805YC224JAT2A" 0805_HV 1378,1884 r270 bottom
C53 "GRM188R71E105KA12D" 0603#1 815,1515 r0 bottom
C54 "C0603C104J3RACTU" 0603#1 1299,1590 r270 bottom
C55 "C0603C104J3RACTU" 0603#1 837,1786 r0 bottom
C56 "GRM188R71E105KA12D" 0603#1 1267.13,288.73 r0 bottom
C57 "GRM188R60J226MEA0J" 0603#2 1384,2085 r0 bottom
C58 "GRM188R60J226MEA0J" 0603#2 1384,2150 r0 bottom
C59 "GRM155R71C104KA88D" 0402 2050,2015 r270 bottom
C60 "C0603C104J3RACTU" 0603#1 949,1654 r90 bottom
C61 "C0603C100F5GAC7867" 0603#1 1170,1888 r270 bottom
C62 "GRM188R71E105KA12D" 0603#1 1638,2474.19 r0 bottom
C63 "GRM188R71E105KA12D" 0603#1 1735,2509.19 r270 bottom
C64 "GRM21BR71A106KE51L" 0805_HV 251,2209 r180 bottom
C65 "GRM188R71E105KA12D" 0603#1 847,2149 r180 bottom
C66 "GRM155R71H103KA88D" 0402 1368,2253 r270 bottom
C67 "GRM1885C1H102FA01J" 0603#1 1156,2163 r90 bottom
C68 "C0805C103F1GACTU" 0805_HV 717,2356 r270 bottom
C69 "GRM21BR71A106KE51L" 0805_HV 1668,2099 r180 bottom
C70 "GRM188R71E105KA12D" 0603#1 847,2451 r180 bottom
C71 "GRM155R71H103KA88D" 0402 1369,2358 r90 bottom
C72 "GRM188R71E105KA12D" 0603#1 1403,2444 r180 bottom
C73 "GRM1885C1H102FA01J" 0603#1 1156,2456 r90 bottom
C74 "GRM188R71E105KA12D" 0603#1 544,1712.02 r180 bottom
C75 "GRM155R71C104KA88D" 0402 3380,1230 r180 bottom
C76 "GRM21BR71A106KE51L" 0805_HV 245,2506 r180 bottom
C77 "C0603C104J3RACTU" 0603#1 405,1600.02 r90 bottom
C78 "GRM155R71C104KA88D" 0402 3130,1040 r90 bottom
C79 "GRM188R71E105KA12D" 0603#1 1192,1349 r270 bottom
C80 "GRM188R71E105KA12D" 0603#1 517,1434.02 r180 bottom
C81 "GRM21BR71A106KE51L" 0805_HV 1006,1249 r0 bottom
C82 "GRM21BR71A106KE51L" 0805_HV 2895.5,626.14 r90 top
C83 "GRM21BR71A106KE51L" 0805_HV 2652.5,1098.94 r90 top
C84 "GRM21BR71A106KE51L" 0805_HV 2895.5,1098.94 r270 top
C85 "GRM155R71C104KA88D" 0402 2462.65,2002.51 r90 bottom
C86 "GRM155R71C104KA88D" 0402 8030,2180 r0 bottom
C87 "GRM21BR71A106KE51L" 0805_HV 6399,1991 r90 top
C88 "GRM21BR71A106KE51L" 0805 1586,1320 r90 bottom
C89 "GRM21BR71A106KE51L" 0805_HV 6156,2444.1 r90 top
C90 "GRM21BR71A106KE51L" 0805_HV 6408.75,2439.3 r270 top
C91 "C3225X5R1A226M" 1210 5569,3741 r90 bottom
C92 "C1005X7R1H102M" 0402 3460,2737 r0 bottom
C93 "C1005X7R1H102M" 0402 3304,2061 r180 top
C94 "C1005X7R1H102M" 0402 2734.62,2416 r0 top
C95 "C1005X7R1H102M" 0402 2584.36,1797.06 r270 top
C96 "ZRB18AD71A106KE01L" 0603_120 3465,2840 r0 bottom
C97 "ZRB18AD71A106KE01L" 0603_120 2469.36,1792.06 r270 top
C98 "GRM155R61A473KA01D" 0402 3459,2789 r0 bottom
C99 "GRM155R61A473KA01D" 0402 3304,2010 r180 top
C100 "GRM155R61A473KA01D" 0402 2734.62,2362 r0 top
C101 "GRM155R61A473KA01D" 0402 2529.36,1797.06 r270 top
C102 "C1005X7R1H102M" 0402 3007,2027 r0 top
C103 "C1005X7R1H102M" 0402 2732,2255 r0 top
C104 "C1005X7R1H102M" 0402 3038,2534.5 r180 top
C105 "C1005X7R1H102M" 0402 3328,2301 r270 top
C106 "ZRB18AD71A106KE01L" 0603_120 3007,2083 r0 top
C107 "ZRB18AD71A106KE01L" 0603_120 3215,2300 r270 top
C108 "GRM155R61A473KA01D" 0402 3007,1974 r0 top
C109 "GRM155R61A473KA01D" 0402 2732,2199 r0 top
C110 "GRM155R61A473KA01D" 0402 3040,2589.5 r180 top
C111 "GRM155R61A473KA01D" 0402 3278,2302 r270 top
C112 "C1005X7R1H102M" 0402 2735,2144 r0 top
C113 "C1005X7R1H102M" 0402 2613,2507 r90 top
C114 "C1005X7R1H102M" 0402 2607,2112 r270 top
C115 "C1005X7R1H102M" 0402 2729,2605 r0 top
C116 "C1005X7R1H102M" 0402 3455,2165 r0 top
C117 "C1005X7R1H102M" 0402 3305,2213 r180 top
C118 "C1005X7R1H102M" 0402 3450,2570 r0 top
C119 "C1005X7R1H102M" 0402 3309,2571 r180 top
C120 "ZRB18AD71A106KE01L" 0603_120 2559,2509 r90 top
C121 "ZRB18AD71A106KE01L" 0603_120 2551,2108 r270 top
C122 "ZRB18AD71A106KE01L" 0603_120 3463,2218 r0 top
C123 "ZRB18AD71A106KE01L" 0603_120 3460,2630 r0 top
C124 "GRM155R61A473KA01D" 0402 2735,2093 r0 top
C125 "GRM155R61A473KA01D" 0402 2736,2042 r0 top
C126 "GRM155R61A473KA01D" 0402 2730,2554 r0 top
C127 "GRM155R61A473KA01D" 0402 2730,2502 r0 top
C128 "GRM155R71C104KA88D" 0402 2575,3746 r270 bottom
C129 "GRM155R61A473KA01D" 0402 3308,2518 r180 top
C130 "GRM155R61A473KA01D" 0402 3307,2468 r180 top
C131 "GRM155R61A473KA01D" 0402 3305,2162 r180 top
C132 "GRM155R61A473KA01D" 0402 3305,2111 r180 top
C133 "GRM155R71C104KA88D" 0402 2395,3791 r180 bottom
C134 "C1005X7R1H102M" 0402 2886.06,1880.36 r180 top
C135 "C1005X7R1H102M" 0402 2895,1974 r180 top
C136 "C1005X7R1H102M" 0402 3137,1872 r0 top
C137 "C1005X7R1H102M" 0402 3136,1972.5 r0 top
C138 "C1005X7R1H102M" 0402 2898,2704.5 r180 top
C139 "C1005X7R1H102M" 0402 3160,2590 r0 top
C140 "C1005X7R1H102M" 0402 3134,2692 r0 top
C141 "C1005X7R1H102M" 0402 2911,2591.5 r180 top
C142 "ZRB18AD71A106KE01L" 0603_120 2889.06,1827.36 r180 top
C143 "ZRB18AD71A106KE01L" 0603_120 3138,1819 r0 top
C144 "ZRB18AD71A106KE01L" 0603_120 3140,2745 r0 top
C145 "ZRB18AD71A106KE01L" 0603_120 2895,2765 r180 top
C146 "GRM155R61A473KA01D" 0402 3134,2029.5 r0 top
C147 "GRM155R61A473KA01D" 0402 3133,2079.5 r0 top
C148 "GRM155R61A473KA01D" 0402 2896,2028 r180 top
C149 "GRM155R61A473KA01D" 0402 2894,2085 r180 top
C150 "GRM155R71C104KA88D" 0402 2730,3781 r270 bottom
C151 "GRM155R61A473KA01D" 0402 2910,2540.5 r180 top
C152 "GRM155R61A473KA01D" 0402 2911,2488.5 r180 top
C153 "GRM155R61A473KA01D" 0402 3158,2487 r0 top
C154 "GRM155R61A473KA01D" 0402 3158,2536 r0 top
C155 "GRM155R71C104KA88D" 0402 2575,3576 r270 bottom
C156 "C1005X7R1H102M" 0402 7774,2592 r0 top
C157 "C1005X7R1H102M" 0402 7070,2280 r270 top
C158 "C1005X7R1H102M" 0402 7665,1925 r270 top
C159 "C1005X7R1H102M" 0402 7615,1926 r270 top
C160 "ZRB18AD71A106KE01L" 0603_120 7775,2697 r0 top
C161 "ZRB18AD71A106KE01L" 0603_120 6836,1734 r270 top
C162 "GRM155R61A473KA01D" 0402 6938,1738 r270 top
C163 "GRM155R61A473KA01D" 0402 6887,1738 r270 top
C164 "GRM155R61A473KA01D" 0402 7020,2280 r270 top
C165 "GRM155R61A473KA01D" 0402 7775,2643 r0 top
C166 "C1005X7R1H102M" 0402 7629,2226 r180 top
C167 "C1005X7R1H102M" 0402 7340,1880 r90 top
C168 "C1005X7R1H102M" 0402 7027,2112 r90 top
C169 "C1005X7R1H102M" 0402 7355,2504 r180 top
C170 "ZRB18AD71A106KE01L" 0603_120 7354,2394 r180 top
C171 "ZRB18AD71A106KE01L" 0603_120 7127,2113 r90 top
C172 "GRM155R61A473KA01D" 0402 7628,2275 r180 top
C173 "GRM155R61A473KA01D" 0402 7291,1881 r90 top
C174 "GRM155R61A473KA01D" 0402 7076,2112 r90 top
C175 "GRM155R61A473KA01D" 0402 7355,2452 r180 top
C176 "C1005X7R1H102M" 0402 6927.64,2006.06 r270 top
C177 "C1005X7R1H102M" 0402 7025.5,1995 r270 top
C178 "C1005X7R1H102M" 0402 6930,2395 r90 top
C179 "C1005X7R1H102M" 0402 7020,2395 r90 top
C180 "C1005X7R1H102M" 0402 7737.64,2441.06 r270 top
C181 "C1005X7R1H102M" 0402 7660,2440 r270 top
C182 "C1005X7R1H102M" 0402 7740,2075 r90 top
C183 "C1005X7R1H102M" 0402 7615,2075 r90 top
C184 "ZRB18AD71A106KE01L" 0603_120 6875,2395 r90 top
C185 "ZRB18AD71A106KE01L" 0603_120 6865,2005 r270 top
C186 "ZRB18AD71A106KE01L" 0603_120 7792.64,2441.06 r270 top
C187 "ZRB18AD71A106KE01L" 0603_120 7795,2075 r90 top
C188 "GRM155R61A473KA01D" 0402 7075.5,1995 r270 top
C189 "GRM155R61A473KA01D" 0402 7125.5,1995 r270 top
C190 "GRM155R61A473KA01D" 0402 7120,2395 r90 top
C191 "GRM155R61A473KA01D" 0402 7070,2395 r90 top
C192 "GRM155R71C104KA88D" 0402 1955,2025 r180 bottom
C193 "GRM155R61A473KA01D" 0402 7560,2440 r270 top
C194 "GRM155R61A473KA01D" 0402 7610,2440 r270 top
C195 "GRM155R61A473KA01D" 0402 7565,2075 r90 top
C196 "GRM155R61A473KA01D" 0402 7665,2075 r90 top
C197 "GRM188R71A105KA61D" 0603#1 1428.8,1317.4 r270 bottom
C198 "C1005X7R1H102M" 0402 7455,1775 r0 top
C199 "C1005X7R1H102M" 0402 7455,1850 r0 top
C200 "C1005X7R1H102M" 0402 7208.5,1780 r180 top
C201 "C1005X7R1H102M" 0402 7210,1855 r180 top
C202 "C1005X7R1H102M" 0402 7227.73,2587.35 r180 top
C203 "C1005X7R1H102M" 0402 7231.38,2505 r180 top
C204 "C1005X7R1H102M" 0402 7470,2585 r0 top
C205 "C1005X7R1H102M" 0402 7470,2500 r0 top
C206 "ZRB18AD71A106KE01L" 0603_120 7455,1720 r0 top
C207 "ZRB18AD71A106KE01L" 0603_120 7208.5,1730 r180 top
C208 "ZRB18AD71A106KE01L" 0603_120 7227.73,2642.35 r180 top
C209 "ZRB18AD71A106KE01L" 0603_120 7470,2640 r0 top
C210 "GRM155R61A473KA01D" 0402 7455,1900 r0 top
C211 "GRM155R61A473KA01D" 0402 7455,1950 r0 top
C212 "GRM155R61A473KA01D" 0402 7210,1955 r180 top
C213 "GRM155R61A473KA01D" 0402 7210,1905 r180 top
C214 "GRM155R71H103KA88D" 0402 1446,2305 r90 bottom
C215 "GRM155R61A473KA01D" 0402 7231.38,2455 r180 top
C216 "GRM155R61A473KA01D" 0402 7231.38,2405 r180 top
C217 "GRM155R61A473KA01D" 0402 7470,2450 r0 top
C218 "GRM155R61A473KA01D" 0402 7470,2400 r0 top
C219 "ZRB18AD71A106KE01L" 0603_120 1002,2603 r0 bottom
C220 "GRM155R71C104KA88D" 0402 5230,2395 r180 bottom
C221 "GRM155R71H103KA88D" 0402 2730,3656 r90 bottom
C222 "GRM155R71C104KA88D" 0402 5080,2180 r270 bottom
C223 "GRM155R71C104KA88D" 0402 5542,2941 r180 bottom
C224 "GRM155R71C104KA88D" 0402 5770,2907 r0 bottom
C225 "GRM155R71C104KA88D" 0402 5562,2785 r180 bottom
C226 "GRM155R71C104KA88D" 0402 5548,3154 r0 bottom
C227 "GRM155R71H103KA88D" 0402 5464,3044 r90 bottom
C228 "ZRB18AD71A106KE01L" 0603_120 1002,2306 r0 bottom (schematic designator C219)
C229 "GRM155R71C104KA88D" 0402 4590,1118 r180 bottom
C230 "GRM155R71C104KA88D" 0402 4197,1117 r180 bottom
C231 "GRM155R71C104KA88D" 0402 2209.65,2025.51 r270 bottom
C232 "C0603C104J3RACTU" 0603#1 2115,1130 r270 bottom
C233 "ZRB18AD71A106KE01L" 0603_120 2175,1130 r270 bottom
C234 "GRM155R61E104KA87D" 0402 2105,1870 r90 bottom
C235 "GRM155R61E104KA87D" 0402 2155,1870 r90 bottom
C236 "202R18W102KV4E" 1206_190 4370,725 r0 bottom
C237 "293D107X9020E2TE3" 7343-43 3814,3459 r0 top
D1 "MBR0520LT1G" SOD-123 3925,3704 r0 bottom
D2 "MBRS4201T3G" SMC 6816,3539 r180 bottom
D3 "MBR0520LT1G" SOD-123 3927,3403 r0 bottom
D4 "CUS05S40,H3F" sod-323 916,1907 r0 bottom
D5 "150060RS75000" WL-SMCW_RED 3490,1754 r270 bottom
D6 "150060RS75000" WL-SMCW_RED 8139,1709 r180 bottom
D7 "150060RS75000" WL-SMCW_RED 4966,3816 r0 bottom
D8 "150060RS75000" WL-SMCW_RED 7276,3990 r270 bottom
D9 "150060RS75000" WL-SMCW_RED 3227,3055 r90 bottom
D10 "150060RS75000" WL-SMCW_RED 3157,3056 r90 bottom
D11 "150060RS75000" WL-SMCW_RED 3375,3056 r90 bottom
D12 "150060RS75000" WL-SMCW_RED 3301,3056 r90 bottom
D13 "150060RS75000" WL-SMCW_RED 3519,3121 r270 bottom
D14 "150060RS75000" WL-SMCW_RED 7530,540 r270 bottom
D15 "150060RS75000" WL-SMCW_RED 660,3009 r180 bottom
D16 "150060RS75000" WL-SMCW_RED 6564.87,286.37 r180 bottom
D17 "150060RS75000" WL-SMCW_RED 2427.56,3402.24 r270 bottom
D18 "150060RS75000" WL-SMCW_RED 7203.78,559.03 r180 bottom
D19 "150060RS75000" WL-SMCW_RED 1376,2809 r180 bottom
D20 "APT2012LZGCK" APT2012_Green 2110,3756 r270 bottom
D21 "APT2012LZGCK" APT2012_Green 5710,3112 r90 bottom
D22 "150060RS75000" WL-SMCW_RED 8820,1200 r0 bottom
D23 "150060RS75000" WL-SMCW_RED 8820,1030 r0 bottom
D24 "150060RS75000" WL-SMCW_RED 8820,738.5 r0 bottom
D25 "150060RS75000" WL-SMCW_RED 8820,880 r0 bottom
FID1 "Fiducial" Fiducial10-20 8810,520 r90 top
FID2 "Fiducial" Fiducial10-20 8810,520 r90 bottom
FID3 "Fiducial" Fiducial10-20 8525,3755 r90 top
FID4 "Fiducial" Fiducial10-20 8525,3755 r90 bottom
FID5 "Fiducial" Fiducial10-20 365,3740 r90 top
FID6 "Fiducial" Fiducial10-20 365,3740 r90 bottom
FID7 "Fiducial" Fiducial10-20 320,425 r90 top (schematic designator FID5)
FID8 "Fiducial" Fiducial10-20 320,425 r90 bottom (schematic designator FID6)
H1 "PMSSS 440 0025 PH" B_F_PMSSS4400025PH 200,4000 r0 bottom
H2 "PMSSS 440 0025 PH" B_F_PMSSS4400025PH 200,200 r0 bottom
H3 "PMSSS 440 0025 PH" B_F_PMSSS4400025PH 8800,4000 r0 bottom (schematic designator H1)
H4 "PMSSS 440 0025 PH" B_F_PMSSS4400025PH 8800,200 r0 bottom (schematic designator H1)
H5 "9774050360R" Wurth_WA-SMSI 2594,1494.44 r180 bottom locked (schematic designator H9)
H6 "9774050360R" Wurth_WA-SMSI 2601,202.44 r180 bottom locked (schematic designator H10)
H7 "9774050360R" Wurth_WA-SMSI 5301,1518.44 r180 bottom locked (schematic designator H9)
H8 "9774050360R" Wurth_WA-SMSI 5304.94,166.78 r180 bottom locked (schematic designator H10)
H9 "1902C" Keystone_1902C 200,200 r0 top
H10 "1902C" Keystone_1902C 200,4000 r0 top
H11 "1902C" Keystone_1902C 4700,200 r0 top
H12 "1902C" Keystone_1902C 4700,4000 r0 top
H13 "9774050360R" Wurth_WA-SMSI 6107.75,2868.12 r180 bottom (schematic designator H9)
H14 "9774050360R" Wurth_WA-SMSI 6107.75,1577.12 r180 bottom locked (schematic designator H10)
H15 "9774050360R" Wurth_WA-SMSI 8807.75,2898.12 r180 bottom locked (schematic designator H9)
H16 "9774050360R" Wurth_WA-SMSI 8801.86,1550.68 r180 bottom locked (schematic designator H10)
H17 "PMSSS 440 0025 PH" B_F_PMSSS4400025PH 4700,200 r0 bottom (schematic designator H1)
H18 "PMSSS 440 0025 PH" B_F_PMSSS4400025PH 4700,4000 r0 bottom (schematic designator H1)
H19 "1902C" Keystone_1902C 8800,200 r0 top
H20 "1902C" Keystone_1902C 8800,4000 r0 top
H21 "PMSSS 440 0025 PH" B_F_PMSSS4400025PH 8635,3145 r180 bottom (schematic designator H1)
H30 "1902C" Keystone_1902C 8634,3141 r0 top
J1 "TSW-123-07-G-D" Samtec_TSW-123-07-x-D#1 7334,3141 r90 top locked
J2 "TSW-123-07-G-D" Samtec_TSW-123-07-x-D#2 8444,1241 r90 top locked
J3 "QTH-030-03-L-D-A" Samtec_QTH-030-01-x-D-A 2774,852.74 r90 bottom locked
J4 "61300211121" WURTH_61300211121 2070,770 r90 bottom
J5 "ED120/2DS" CONN_ED120-2DS 6878,4012 r90 bottom
J6 "TSM-103-01-L-SV" Samtec_TSM-103-01-X-SV 530,2180 r270 bottom
J7 "142-0701-801" JOHNSON_142-0701-801 107,1901 r270 bottom
J8 "142-0701-801" JOHNSON_142-0701-801 107,2803 r270 bottom
J9 "TSM-103-01-L-SV" Samtec_TSM-103-01-X-SV 532,2533 r270 bottom
J10 "87898-0204" Molex_87898-0204 631,1173 r180 bottom
J11 "87898-0204" Molex_87898-0204 229,1305.02 r180 bottom
J12 "61300311121" WURTH_61300311121 1137,3187 r0 bottom
J13 "61300311121" WURTH_61300311121 1625,3182 r180 bottom
J14 "PEC06SAAN" Sullins_PEC06SAAN 2465,3020 r0 bottom
J16 "HTSW-103-07-G-S" Samtec_HTSW-103-07-G-S 3005,3040 r90 bottom
J17 "HTSW-103-07-G-S" Samtec_HTSW-103-07-G-S 6050,665 r270 bottom
J18 "QTH-030-03-L-D-A" Samtec_QTH-030-01-x-D-A 6277.5,2217.6 r90 bottom
J19 "PEC06SAAN" Sullins_PEC06SAAN 5718.5,2165 r270 bottom
J21 "61300211121" WURTH_61300211121 4980,2210 r90 bottom
J22 "HTSW-103-07-G-S" Samtec_HTSW-103-07-G-S 2865,3035 r90 bottom
J24 "HTSW-103-07-G-S" Samtec_HTSW-103-07-G-S 2320,2680 r180 bottom
J25 "61300211121" WURTH_61300211121 3732,3926 r180 bottom
L1 "HZ0805E601R-10" 0805_HV 8240,965 r90 top
L2 "MPZ2012S601A" 0805_HV 5379,3665 r180 bottom
LBL1 "Size: 0.65\" x 0.20 \"" Label_650x200 8051,558 r0 bottom
Logo1 "Texas Instruments" TI_Stacked_Overlay_Small 7971.45,945.9 r180 bottom
Q1 "CMPT3904 LEAD FREE" SOT-23 683,3124 r0 bottom
Q2 "CMPT3904 LEAD FREE" SOT-23 6622.87,155.37 r90 bottom
Q3 "CMPT3904 LEAD FREE" SOT-23 2320,3480 r270 bottom
Q4 "CMPT3904 LEAD FREE" SOT-23 7235.78,446.03 r90 bottom
Q5 "CMPT3904 LEAD FREE" SOT-23 1407,2919 r270 bottom
Q6 "NX3020NAKW,115" SOT-323 2220,3660 r180 bottom
Q7 "NX3020NAKW,115" SOT-323 5814,3127 r90 bottom
R1 "CRCW040210R0FKED" 0402 8390,2960 r90 bottom
R2 "CRCW040210R0FKED" 0402 8440,2960 r270 bottom
R3 "CRCW040210R0FKED" 0402 8290,2960 r90 bottom
R4 "CRCW040210R0FKED" 0402 8340,2960 r270 bottom
R5 "CRCW040210R0FKED" 0402 8190,2960 r90 bottom
R6 "CRCW040210R0FKED" 0402 8240,2960 r270 bottom
R7 "CRCW040210R0FKED" 0402 8090,2960 r90 bottom
R8 "CRCW040210R0FKED" 0402 8140,2960 r270 bottom
R9 "CRCW040210R0FKED" 0402 7990,2960 r90 bottom
R10 "CRCW040210R0FKED" 0402 8040,2960 r270 bottom
R11 "CRCW040210R0FKED" 0402 7890,2960 r90 bottom
R12 "CRCW040210R0FKED" 0402 7940,2960 r270 bottom
R13 "CRCW040210R0FKED" 0402 7790,2960 r90 bottom
R14 "CRCW040210R0FKED" 0402 7840,2960 r270 bottom
R15 "CRCW040210R0FKED" 0402 7690,2960 r90 bottom
R16 "CRCW040210R0FKED" 0402 7740,2960 r270 bottom
R17 "CRCW040210R0FKED" 0402 7590,2960 r90 bottom
R18 "CRCW040210R0FKED" 0402 7640,2960 r270 bottom
R19 "CRCW040210R0FKED" 0402 7490,2960 r90 bottom
R20 "CRCW040210R0FKED" 0402 7540,2960 r270 bottom
R21 "CRCW040210R0FKED" 0402 7390,2960 r90 bottom
R22 "CRCW040210R0FKED" 0402 7440,2960 r270 bottom
R23 "CRCW040210R0FKED" 0402 7290,2960 r90 bottom
R24 "CRCW040210R0FKED" 0402 7340,2960 r270 bottom
R25 "CRCW040210R0FKED" 0402 7190,2960 r90 bottom
R26 "CRCW040210R0FKED" 0402 7240,2960 r270 bottom
R27 "CRCW040210R0FKED" 0402 7090,2960 r90 bottom
R28 "CRCW040210R0FKED" 0402 7140,2960 r270 bottom
R29 "CRCW040210R0FKED" 0402 6990,2960 r90 bottom
R30 "CRCW040210R0FKED" 0402 7040,2960 r270 bottom
R31 "CRCW040210R0FKED" 0402 6890,2960 r90 bottom
R32 "CRCW040210R0FKED" 0402 6940,2960 r270 bottom
R33 "CRCW040210R0FKED" 0402 6790,2960 r90 bottom
R34 "CRCW040210R0FKED" 0402 6840,2960 r270 bottom
R35 "CRCW040210R0FKED" 0402 6690,2960 r90 bottom
R36 "CRCW040210R0FKED" 0402 6740,2960 r270 bottom
R37 "CRCW040210R0FKED" 0402 6590,2960 r90 bottom
R38 "CRCW040210R0FKED" 0402 6640,2960 r270 bottom
R39 "CRCW040210R0FKED" 0402 6492,2959 r90 bottom
R40 "CRCW040210R0FKED" 0402 6540,2960 r270 bottom
R41 "CRCW040210R0FKED" 0402 6392,2959 r90 bottom
R42 "CRCW040210R0FKED" 0402 6443,2958 r270 bottom
R43 "CRCW040210R0FKED" 0402 6294,2957.62 r90 bottom
R44 "CRCW040210R0FKED" 0402 6343,2957 r270 bottom
R45 "CRCW04020000Z0ED" 0402 1835,2180 r0 bottom
R46 "ERJ-3RQFR22V" 0603#1 1660,1651 r270 bottom
R47 "ERJ-3RQFR22V" 0603#1 1498,1318 r90 bottom
R48 "ERJ-3GEY0R00V" 0603#1 1491,1835 r180 bottom
R49 "ERJ-3GEY0R00V" 0603#1 1500,1930 r180 bottom
R50 "CRCW08051K50JNEA" 0805_HV 4696,963 r270 bottom
R51 "CRCW12060000Z0EA" 1206 3739,3818 r180 bottom
R52 "ERJ-3RSFR10V" 0603#1 1219,3524 r90 bottom
R53 "ERJ-2GE0R00X" 0402 1030.52,3432.92 r90 bottom
R54 "ERJ-2GE0R00X" 0402 980.52,3432.92 r90 bottom
R55 "ERJ-2GE0R00X" 0402 929.08,3431.52 r90 bottom
R56 "ERJ-2GE0R00X" 0402 844.52,3595.92 r0 bottom
R57 "ERJ-2GE0R00X" 0402 844.52,3645.92 r0 bottom
R58 "ERJ-2GE0R00X" 0402 844.52,3695.92 r0 bottom
R59 "ERJ-2GE0R00X" 0402 981,3824.38 r270 bottom
R60 "ERJ-2GE0R00X" 0402 1031,3824.38 r270 bottom
R61 "ERJ-2RKF1002X" 0402 4646.01,1606.99 r90 bottom
R62 "ERJ-2RKF1002X" 0402 4111.01,1606.99 r270 bottom
R63 "ERJ-3RSFR10V" 0603#1 3414,3472 r90 bottom
R64 "ERJ-2GE0R00X" 0402 3242.18,3420.46 r90 bottom
R65 "ERJ-2GE0R00X" 0402 3192.18,3420.46 r90 bottom
R66 "ERJ-2GE0R00X" 0402 3139.54,3421.18 r90 bottom
R67 "ERJ-2GE0R00X" 0402 3067.18,3591.46 r0 bottom
R68 "ERJ-2GE0R00X" 0402 3067.18,3641.46 r0 bottom
R69 "ERJ-2GE0R00X" 0402 3067.18,3691.46 r0 bottom
R70 "ERJ-2GE0R00X" 0402 3189.18,3809.84 r270 bottom
R71 "ERJ-2GE0R00X" 0402 3239.18,3809.84 r270 bottom
R72 "ERJ-2RKF1002X" 0402 4646,2135.98 r90 bottom
R73 "ERJ-2RKF1002X" 0402 4111,2140.98 r270 bottom
R74 "ERJ-2RKF1002X" 0402 4649,2973 r90 bottom
R75 "ERJ-2RKF1002X" 0402 4119,2973 r270 bottom
R76 "ERJ-3RSFR10V" 0603#1 4947.25,3145.3 r270 top
R77 "ERJ-2GE0R00X" 0402 5138.25,2987.76 r90 top
R78 "ERJ-2GE0R00X" 0402 5188.25,2987.76 r90 top
R79 "ERJ-2GE0R00X" 0402 5238.76,2988.75 r90 top
R80 "ERJ-2GE0R00X" 0402 5322.25,3155.76 r180 top
R81 "ERJ-2GE0R00X" 0402 5322.25,3205.76 r180 top
R82 "ERJ-2GE0R00X" 0402 5322.25,3255.76 r180 top
R83 "ERJ-2GE0R00X" 0402 5201.25,3374.76 r270 top
R84 "ERJ-2GE0R00X" 0402 5151.25,3374.76 r270 top
R85 "RG1608P-102-B-T5" 0603#1 815,1450 r180 bottom
R86 "RG1608P-2491-B-T5" 0603#1 1127,1622 r0 bottom
R87 "CRCW0402100KFKED" 0402 1238.13,403.73 r90 bottom
R88 "RG1608P-4991-B-T5" 0603#1 1233,1590 r90 bottom
R89 "CRCW06034R75FKEA" 0603#1 1298,1886 r90 bottom
R90 "ERJ-2RKF1002X" 0402 1294.13,403.73 r90 bottom
R91 "RG1608P-102-B-T5" 0603#1 1051,1744 r90 bottom
R92 "RG1608P-4990-B-T5" 0603#1 1234,1887 r90 bottom
R93 "ERJ-2RKF1002X" 0402 1564.13,568.73 r180 bottom
R94 "RG1608P-303-B-T5" 0603#1 950,1801 r90 bottom
R95 "CRCW06032R21FKEA" 0603#1 1274,2266 r0 bottom
R96 "RG1608P-101-B-T5" 0603#1 251,2290 r0 bottom
R97 "ERJ-3GEY0R00V" 0603#1 425,1895 r0 bottom
R98 "RG1608P-102-B-T5" 0603#1 847,2212 r0 bottom
R99 "RG1608P-102-B-T5" 0603#1 1090,2163 r270 bottom
R100 "ERJ-2RKF1002X" 0402 1680,1996 r0 bottom
R101 "CRCW06032R21FKEA" 0603#1 1274,2335 r0 bottom
R102 "ERJ-2GE0R00X" 0402 1498,2465 r90 bottom
R103 "ERJ-3GEY0R00V" 0603#1 424,2805 r0 bottom
R104 "RG1608P-102-B-T5" 0603#1 847,2517 r0 bottom
R105 "RG1608P-102-B-T5" 0603#1 1090,2458 r270 bottom
R106 "RG1608P-203-B-T5" 0603#1 544,1776 r0 bottom
R107 "RC0603FR-071KL" 0603#1 3035,3230 r0 bottom
R108 "RG1608P-101-B-T5" 0603#1 285,2395 r270 bottom
R109 "RG2012P-2803-B-T5" 0805_HV 506,1280 r0 bottom
R110 "RG1608P-4990-B-T5" 0603#1 642,1745 r90 bottom
R111 "RG1608P-203-B-T5" 0603#1 648,1370 r180 bottom
R112 "RG1608P-103-B-T5" 0603#1 518,1501.02 r0 bottom
R113 "ERJ-3RQFR22V" 0603#1 850,1315 r90 bottom
R114 "RG1608P-203-B-T5" 0603#1 515,1368.02 r0 bottom
R115 "RG1608P-101-B-T5" 0603#1 2696,2834 r270 bottom
R116 "RG1608P-101-B-T5" 0603#1 2630,1900 r0 top
R117 "RG1608P-101-B-T5" 0603#1 2630,1965 r0 top
R118 "RG1608P-101-B-T5" 0603#1 2630,2833 r270 bottom
R119 "RC0603FR-071KL" 0603#1 3325.8,1579 r270 bottom
R120 "RC0603FR-071KL" 0603#1 3390.8,1579 r90 bottom
R121 "RC0603FR-071KL" 0603#1 2564,2832 r270 bottom
R122 "RC0603FR-071KL" 0603#1 3550,2040 r180 bottom
R123 "CRCW040210R0FKED" 0402 7982.5,1409 r270 bottom
R124 "CRCW040210R0FKED" 0402 7929.5,1409 r90 bottom
R125 "CRCW040210R0FKED" 0402 7878.5,1409 r270 bottom
R126 "CRCW040210R0FKED" 0402 7827.5,1409 r90 bottom
R127 "CRCW040210R0FKED" 0402 7777.5,1407 r270 bottom
R128 "CRCW040210R0FKED" 0402 7728.5,1408 r90 bottom
R129 "CRCW040210R0FKED" 0402 7677.5,1408 r270 bottom
R130 "CRCW040210R0FKED" 0402 7627.5,1408 r90 bottom
R131 "CRCW040210R0FKED" 0402 7577.5,1407 r270 bottom
R132 "CRCW040210R0FKED" 0402 7527.5,1407 r90 bottom
R133 "CRCW040210R0FKED" 0402 7478.5,1407 r270 bottom
R134 "CRCW040210R0FKED" 0402 7428.5,1407 r90 bottom
R135 "CRCW040210R0FKED" 0402 7378.5,1406 r270 bottom
R136 "CRCW040210R0FKED" 0402 7329.5,1406 r90 bottom
R137 "CRCW040210R0FKED" 0402 7280.5,1406 r270 bottom
R138 "CRCW040210R0FKED" 0402 7229.5,1406 r90 bottom
R139 "CRCW040210R0FKED" 0402 7180.5,1405 r270 bottom
R140 "CRCW040210R0FKED" 0402 7131.5,1404 r90 bottom
R141 "CRCW040210R0FKED" 0402 7081.5,1404 r270 bottom
R142 "CRCW040210R0FKED" 0402 7032.5,1404 r90 bottom
R143 "CRCW040210R0FKED" 0402 6982.5,1404 r270 bottom
R144 "CRCW040210R0FKED" 0402 6838,1402 r270 bottom
R145 "CRCW040210R0FKED" 0402 6786,1402 r270 bottom
R146 "CRCW040210R0FKED" 0402 6735,1400 r90 bottom
R147 "CRCW040210R0FKED" 0402 6685,1400 r270 bottom
R148 "CRCW040210R0FKED" 0402 6635,1399 r90 bottom
R149 "CRCW040210R0FKED" 0402 6583,1399 r270 bottom
R150 "CRCW040210R0FKED" 0402 6534,1399 r90 bottom
R151 "CRCW040210R0FKED" 0402 6481,1398 r270 bottom
R152 "CRCW040210R0FKED" 0402 6430,1398 r90 bottom
R153 "RC0603FR-071KL" 0603#1 2517,2905 r90 top
R154 "RC0603FR-071KL" 0603#1 3680.2,2852 r270 bottom
R155 "RC0603FR-071KL" 0603#1 2309,2905 r90 top
R156 "RC0603FR-071KL" 0603#1 3618.2,2854 r270 bottom
R157 "RC0603FR-071KL" 0603#1 2412,2905 r90 top
R158 "RC0603FR-071KL" 0603#1 3748.2,2850 r270 bottom
R159 "RC0603FR-071KL" 0603#1 2218,2905 r90 top
R160 "ERJ-2GE0R00X" 0402 2485,590 r0 bottom
R161 "CRCW040233R0JNED" 0402 2360,1895 r0 bottom
R162 "ERJ-2GE0R00X" 0402 2485,640 r0 bottom
R163 "ERJ-2GE0R00X" 0402 2485,690 r0 bottom
R164 "ERJ-2GE0R00X" 0402 2485,740 r0 bottom
R165 "RC0603FR-071KL" 0603#1 3256.8,1578 r90 bottom
R166 "ERJ-2GE0R00X" 0402 2485,790 r0 bottom
R167 "CRCW040233R0JNED" 0402 2370,2110 r180 bottom
R168 "RC0603FR-071KL" 0603#1 3557,1764 r90 bottom
R169 "ERJ-2GE0R00X" 0402 2485,840 r0 bottom
R170 "ERJ-2GE0R00X" 0402 2485,890 r0 bottom
R171 "ERJ-2GE0R00X" 0402 2485,940 r0 bottom
R172 "ERJ-2GE0R00X" 0402 2485,990 r0 bottom
R173 "ERJ-2GE0R00X" 0402 2485,1040 r0 bottom
R174 "RC0603FR-071KL" 0603#1 3878.2,2850 r270 bottom
R175 "ERJ-2GE0R00X" 0402 2485,1090 r0 bottom
R176 "RC0603FR-071KL" 0603#1 3942.2,2849 r270 bottom
R177 "RC0603FR-071KL" 0603#1 4005,2850 r90 bottom
R178 "RC0603FR-071KL" 0603#1 3814.2,2850 r270 bottom
R179 "CRCW040233R0JNED" 0402 8155,2145 r90 bottom
R180 "CRCW040233R0JNED" 0402 7941,2076 r90 bottom
R181 "RC0603FR-071KL" 0603#1 7995,2557 r180 top
R182 "RC0603FR-071KL" 0603#1 7995,2621 r180 top
R183 "RC0603FR-071KL" 0603#1 7995,2493 r180 top
R184 "RC0603FR-071KL" 0603#1 8150,1581 r0 bottom
R185 "RC0603FR-071KL" 0603#1 8148,1516 r180 bottom
R186 "ERJ-2GE0R00X" 0402 5979,1953.8 r0 bottom
R187 "RC0603FR-071KL" 0603#1 8150,1773 r0 bottom
R188 "RC0603FR-071KL" 0603#1 8147.5,1645 r180 bottom
R189 "ERJ-2GE0R00X" 0402 5979,2002.8 r0 bottom
R190 "ERJ-2GE0R00X" 0402 5980,2051.8 r0 bottom
R191 "RC0603FR-071KL" 0603#1 7030.02,2592.35 r180 top
R192 "RG1608P-101-B-T5" 0603#1 6692,2551 r0 bottom
R193 "ERJ-2GE0R00X" 0402 5980,2100.8 r0 bottom
R194 "RG1608P-101-B-T5" 0603#1 7016,1643 r90 bottom
R195 "ERJ-2GE0R00X" 0402 5981,2149.8 r0 bottom
R196 "RC0603FR-071KL" 0603#1 7872,1898 r90 top
R197 "RG1608P-101-B-T5" 0603#1 6887,1833 r0 top
R198 "RG1608P-101-B-T5" 0603#1 6691,2616 r0 bottom
R199 "ERJ-2GE0R00X" 0402 5982,2198.8 r0 bottom
R200 "ERJ-2GE0R00X" 0402 5983,2247.8 r0 bottom
R201 "RC0603FR-071KL" 0603#1 5586.5,2113 r0 top
R202 "RC0603FR-071KL" 0603#1 5586.5,2314 r0 top
R203 "RC0603FR-071KL" 0603#1 5586.5,2211 r0 top
R204 "CRCW08051K50JNEA" 0805_HV 4101,1126 r90 bottom
R205 "CRCW08051K50JNEA" 0805_HV 4694,1123 r90 bottom
R206 "CRCW08051K50JNEA" 0805_HV 4101,966 r270 bottom
R207 "RC0603FR-0733RL" 0603#1 4055,2260 r180 bottom
R208 "ERJ-2GE0R00X" 0402 1635,2531.19 r180 bottom
R209 "RC0603JR-07330RL" 0603#1 8695,1230 r270 bottom
R210 "ERJ-2GE0R00X" 0402 5983,2297.8 r0 bottom
R211 "RC0603FR-071KL" 0603#1 5586.5,2416 r0 top
R212 "ERJ-2GE0R00X" 0402 5982,2346.8 r0 bottom
R213 "ERJ-2GE0R00X" 0402 5982,2395.8 r0 bottom
R214 "RC0603FR-071KL" 0603#1 7995,2367 r180 top
R215 "ERJ-2GE0R00X" 0402 5982,2444.8 r0 bottom
R216 "RC0603FR-071KL" 0603#1 7995,2303 r180 top
R217 "RC0603FR-071KL" 0603#1 7994,2239 r0 top
R218 "RC0603FR-071KL" 0603#1 7995.72,2430 r180 top
R219 "RT0805BRD07118KL" 0805_HV 5859,3451 r270 bottom
R220 "RT0805BRD075K62L" 0805_HV 5578,3555 r180 bottom
R221 "CRCW0805249KFKEA" 0805_HV 5987,3486 r0 bottom
R222 "CRCW06031K20JNEA" 0603#1 4996,3711 r270 bottom
R223 "RT0805BRD071K07L" 0805_HV 5578,3375 r0 bottom
R224 "CRCW080520K5FKEA" 0805_HV 5762,3449 r90 bottom
R225 "WSL0805R0100FEA18" 0805_HV 5581,3284 r180 bottom
R226 "CRCW06031K20JNEA" 0603#1 7276,3870 r270 bottom
R227 "RC0603JR-07330RL" 0603#1 3228,2910 r90 bottom
R228 "RC0603JR-07330RL" 0603#1 3155,2913 r90 bottom
R229 "RC0603JR-07330RL" 0603#1 3370,2913 r90 bottom
R230 "RC0603JR-07330RL" 0603#1 3297,2913 r90 bottom
R231 "CRCW06031K20JNEA" 0603#1 3592,3127 r90 bottom
R232 "CRCW06031K20JNEA" 0603#1 7529,418 r270 bottom
R233 "CRCW06031K20JNEA" 0603#1 670,2939 r0 bottom
R234 "RC0603JR-07330RL" 0603#1 560,3118 r90 bottom
R235 "CRCW06031K20JNEA" 0603#1 6508.87,152.37 r270 bottom
R236 "CRCW06031K20JNEA" 0603#1 2495,3405 r90 bottom
R237 "RC0603JR-07330RL" 0603#1 6727.87,144.37 r90 bottom
R238 "RC0603JR-07330RL" 0603#1 2215,3495 r270 bottom
R239 "CRCW06031K20JNEA" 0603#1 7115.78,524.03 r270 bottom
R240 "CRCW06031K20JNEA" 0603#1 1279,2838 r90 bottom
R241 "RC0603JR-07330RL" 0603#1 7235.78,332.03 r180 bottom
R242 "RC0603JR-07330RL" 0603#1 1371,3064 r90 bottom
R243 "RC0603FR-071KL" 0603#1 2835,3225 r180 bottom
R244 "RC0603FR-07511RL" 0603#1 1564,834 r90 bottom
R246 "CRCW060310K0FKEA" 0603#1 3200,1040 r270 bottom
R247 "ERJ-2RKF1002X" 0402 2110,3896 r90 bottom
R248 "RG1608P-3242-B-T5" 0603_HV 2755,3866 r0 bottom
R249 "RG1608P-103-B-T5" 0603_HV 2785,3776 r90 bottom
R250 "ERJ-2RKF1002X" 0402 2320,3711 r270 bottom
R251 "CRCW060310K0FKEA" 0603#1 5140,2190 r90 bottom
R252 "RG1608P-103-B-T5" 0603_HV 2760,3561 r180 bottom
R253 "RG1608P-2552-B-T5" 0603_HV 2790,3651 r270 bottom
R254 "ERJ-2RKF1002X" 0402 5638,3091 r90 bottom
R255 "RG1608P-3242-B-T5" 0603_HV 5647,2756 r270 bottom
R256 "RG1608P-103-B-T5" 0603_HV 5562,2730 r0 bottom
R257 "ERJ-2RKF1002X" 0402 5841,2984 r90 bottom
R258 "RG1608P-103-B-T5" 0603_HV 5431,2951 r180 bottom
R259 "RG1608P-2552-B-T5" 0603_HV 5407,3046 r270 bottom
R260 "RC0603FR-0733RL" 0603#1 4680,2260 r180 bottom
R261 "CRCW04020000Z0ED" 0402 1835,2130 r0 bottom
R264 "RC0603JR-07330RL" 0603#1 8695,1060 r270 bottom
R265 "RC0603JR-07330RL" 0603#1 8695,768.5 r270 bottom
R266 "RC0603JR-07330RL" 0603#1 8695,915 r270 bottom
R267 "CRCW04024K70JNED" 0402 2005,1165 r0 bottom
R268 "ERJ-2BSFR10X" 0402 1504,2150 r0 bottom
R269 "CRCW040233R0JNED" 0402 2170,2175 r0 bottom
R270 "CRCW04024K70JNED" 0402 2235,1350 r90 bottom
R271 "CRCW04024K70JNED" 0402 1885,1355 r90 bottom
R273 "CRCW040233R0JNED" 0402 2170,2125 r0 bottom
R274 "CRCW0402100RJNED" 0402 2130,1950 r180 bottom
R276 "ERJ-2BSFR10X" 0402 1504,2085 r0 bottom
R277 "CRCW04024K70JNED" 0402 2005,1115 r0 bottom
S1 "EVQPNF04M" SW_EVQPNF04M 1114.33,395.73 r270 bottom
T1 "750315240" Wurth_750315240 4393,3556 r180 bottom
TP1 "TP1_PD40_D0.5_S50" TP-040_RND 1330,3565 r90 bottom
TP2 "TP1_PD40_D0.5_S50" TP-040_RND 4996,3556 r0 bottom
TP3 "5016" Testpoint_Keystone_Compact 3730,3501 r270 bottom
TP4 "TP1_PD40_D0.5_S50" TP-040_RND 6310.93,830.04 r90 top
TP5 "TP1_PD40_D0.5_S50" TP-040_RND 6325.93,225.04 r90 top
TP6 "TP1_PD40_D0.5_S50" TP-040_RND 3528,3519 r90 bottom
TP7 "TP1_PD40_D0.5_S50" TP-040_RND 1842.5,3295 r270 bottom
TP8 "TP1_PD40_D0.5_S50" TP-040_RND 1857.5,3923 r270 bottom
TP9 "TP1_PD40_D0.5_S50" TP-040_RND 5712.35,871.88 r90 top
TP10 "TP1_PD40_D0.5_S50" TP-040_RND 5696.95,240.02 r180 top
TP11 "TP1_PD40_D0.5_S50" TP-040_RND 558.5,3248 r180 bottom
TP12 "TP1_PD40_D0.5_S50" TP-040_RND 1403,3183 r180 bottom
TP13 "TP1_PD40_D0.5_S50" TP-040_RND 574.5,3875 r180 bottom
TP14 "TP1_PD40_D0.5_S50" TP-040_RND 1534.5,3920 r180 bottom
TP15 "TP-025-SMT" TP_25MIL-SMT 8030,1081 r90 top
TP16 "5016" Testpoint_Keystone_Compact 6026,3272 r180 bottom
TP17 "TP1_PD40_D0.5_S50" TP-040_RND 4947.25,3013.3 r180 top
TP18 "TP-025-SMT" TP_25MIL-SMT 6583,1475 r90 bottom
TP19 "TP-025-SMT" TP_25MIL-SMT 6685,1475 r90 bottom
TP20 "TP-025-SMT" TP_25MIL-SMT 6785,1475 r90 bottom
TP21 "TP-025-SMT" TP_25MIL-SMT 6838,1475 r90 bottom
TP22 "TP-025-SMT" TP_25MIL-SMT 6534,1475 r90 bottom
TP23 "TP-025-SMT" TP_25MIL-SMT 6635,1475 r90 bottom
TP24 "TP-025-SMT" TP_25MIL-SMT 6735,1475 r90 bottom
TP25 "TP-025-SMT" TP_25MIL-SMT 8240,1083 r180 top
TP26 "5016" Testpoint_Keystone_Compact 8385,177 r0 bottom
TP27 "5016" Testpoint_Keystone_Compact 4937,487 r0 bottom
TP28 "5016" Testpoint_Keystone_Compact 5067,4014 r0 bottom
TP29 "5016" Testpoint_Keystone_Compact 8385,4001 r0 bottom
TP30 "TP-025-SMT" TP_25MIL-SMT 8334,1082 r90 top
TP31 "TP-025-SMT" TP_25MIL-SMT 8134,1085 r90 top
TP32 "5016" Testpoint_Keystone_Compact 5362,3867 r180 bottom
TP33 "TP-025-SMT" TP_25MIL-SMT 6764.43,2482.57 r90 bottom
TP34 "TP-025-SMT" TP_25MIL-SMT 6845,2545 r90 bottom
TP35 "5016" Testpoint_Keystone_Compact 7864,177 r180 bottom
TP36 "5016" Testpoint_Keystone_Compact 188,3518 r180 bottom
TP37 "5016" Testpoint_Keystone_Compact 737,145 r180 bottom
TP38 "5016" Testpoint_Keystone_Compact 4015,3887 r180 bottom
TP39 "5016" Testpoint_Keystone_Compact 3846,226 r180 bottom
TP40 "5016" Testpoint_Keystone_Compact 1135,3009 r0 bottom
TP41 "5016" Testpoint_Keystone_Compact 195,3241 r180 bottom
TP42 "5016" Testpoint_Keystone_Compact 7530,177 r0 bottom
TP43 "5016" Testpoint_Keystone_Compact 2090,3330 r90 bottom
TP44 "5016" Testpoint_Keystone_Compact 3903,3165 r270 bottom
TP45 "5016" Testpoint_Keystone_Compact 7205,177 r180 bottom
TP46 "5016" Testpoint_Keystone_Compact 6900,177 r180 bottom
TP47 "5016" Testpoint_Keystone_Compact 1615,2814 r180 bottom
TP48 "TP-025-SMT" TP_25MIL-SMT 2278.65,2118.51 r90 bottom
TP49 "TP-025-SMT" TP_25MIL-SMT 7878,2109 r90 bottom
TP50 "TP-025-SMT" TP_25MIL-SMT 7130,1480 r90 bottom
TP51 "TP-025-SMT" TP_25MIL-SMT 7180,1480 r90 bottom
U1 "SN6505ADBVR" DBV0006A_N 4842.08,3555.52 r0 bottom
U2 "TPS7A4700RGWR" RGW0020A 1047.52,3620.92 r90 bottom
U3 "LMZ14203TZ-ADJ/NOPB" TZA07A_V 5867,3841 r90 bottom
U4 "TPS70912DBVT" DBV0005A_N 1907.5,3615 r270 bottom
U5 "ISO7840DWR" DW0016B_N 4381.01,1756.99 r180 bottom
U6 "TPS70918DBVT" DBV0005A_N 5757.35,571.88 r90 top
U7 "TPS7A4700RGWR" RGW0020A 3257.18,3615.46 r90 bottom
U8 "TPS70918DBVT" DBV0005A_N 628.5,3568 r270 bottom
U9 "ISO7842DWR" DW0016B_N 4381,2285.98 r180 bottom
U10 "TPS70918DBVT" DBV0005A_N 1591.5,3618 r270 bottom
U11 "TPS70912DBVT" DBV0005A_N 6370.93,520.04 r90 top (schematic designator U3)
U12 "ISO7840DWR" DW0016B_N 4384,2823 r0 bottom
U13 "TPS7A4700RGWR" RGW0020A 5126.25,3179.76 r90 top
U14 "OPA378AIDBVT" DBV0005A_N 831,1664 r90 bottom
U15 "OPA625IDBVR" DBV0006A_N 1245,1733 r180 bottom
U16 "SN74LVC1G17DCKR" DCK0005A_N 1580.13,478.23 r0 bottom
U17 "SN74LVC1G08DCKR" DCK0005A_N 1588.13,669.23 r90 bottom
U18 "OPA625IDBVR" DBV0006A_N 984,2186 r90 bottom
U19 "ADS9110IRGER" RGE0024H 1655,2303 r90 bottom
U20 "OPA625IDBVR" DBV0006A_N 984,2483 r90 bottom
U21 "BR24G32FVT-3AGE2" TSOP65P640X120-8N 3318,1051 r90 bottom
U22 "REF5045AIDGKT" DGK0008A_N 1013,1360 r180 bottom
